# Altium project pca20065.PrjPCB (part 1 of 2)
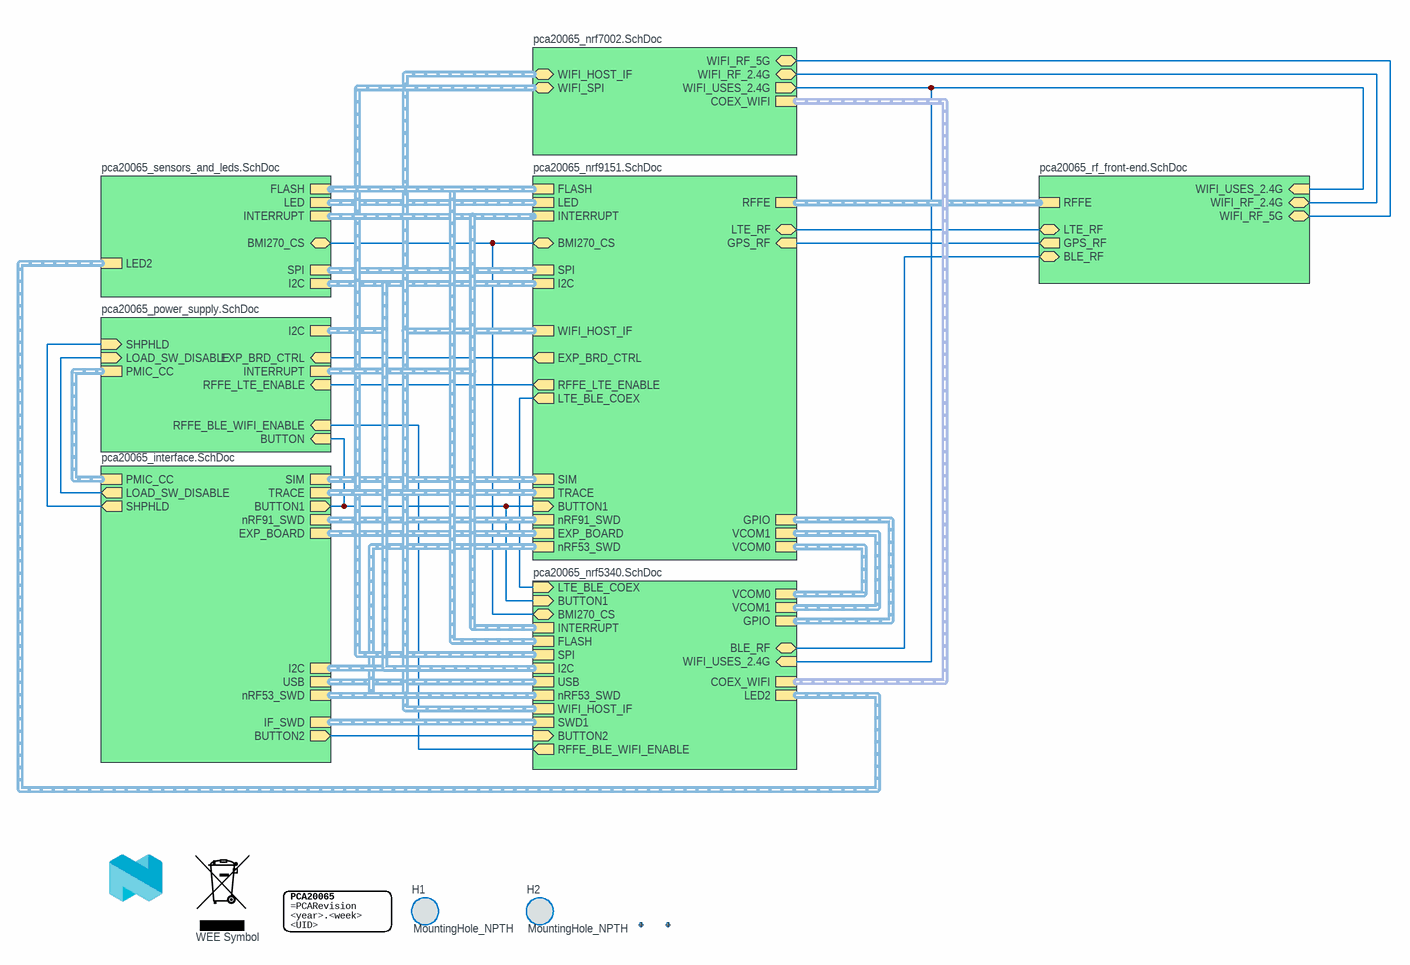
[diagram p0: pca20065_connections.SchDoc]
SurfaceFinish: ENIG Gold; SoldermaskColor: Blue; SilkscreenColor: White; ProjectNumber: 4492; ProjectName: Thingy91v2; ProductName: Thingy:91 X; PCBStackup: 6001; PCBRevision: 0229GETR; PCBNumber: 400796; PCARevision: 2.0.0; PCAName: PCA20065; Organization: Nordic Semiconductor; NrOfLayers: 6; Dielectric: FR-4; Designer: GETR; Compliance: RoHS, REACH, Halogen-Free; Classification: Public; BoardTitle: Thingy:91 X; BoardThickness: 1.6mm
10 sheets, 319 parts. Net scope: hierarchical (ports join the sheet entries above them; power ports are global).
Board file: 400796.PcbDoc
Sheets:
  pca20065_connections.SchDoc
     = pca20065_nrf9151.SchDoc
     = pca20065_sensors_and_leds.SchDoc
     = pca20065_nrf5340.SchDoc
     = pca20065_interface.SchDoc
      S1 = pca20065_switch_fsa.SchDoc
      S9 = pca20065_switch_nx.SchDoc
     = pca20065_power_supply.SchDoc
     = pca20065_rf_front-end.SchDoc
     = pca20065_nrf7002.SchDoc

## Sheet pca20065_connections.SchDoc: =BoardTitle + ' - Connections'
size A3; Organization: Nordic Semiconductor; DocumentNumber: 1; Revision: 2.0.0; SheetNumber: 1; SheetTotal: 10; Author: GETR; CompanyName: Nordic Semiconductor; DrawnBy: GETR; DocumentSize: A3

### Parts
Fid1  Fiducial mark  [Fiducial_Round-Square]  (value not drawn)
Fid2  Fiducial mark  [Fiducial_Round-Square]  (value not drawn)
H1  MountingHole_NPTH  [MountingHole_3.2_M3]  (no BOM)
H2  MountingHole_NPTH  [MountingHole_3.2_M3]  (no BOM)
LABEL1  12x38mm  [LabelSilk_12x38]  (value not drawn)
LOGO1  WEE Symbol  [WEE_3x4.5mm]  (no BOM)
LOGO2  Nordic Logo  [NORDIC_LOGO_LYING]  (value not drawn)  (no BOM)

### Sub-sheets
? = pca20065_nrf9151.SchDoc: SIM (harness SIM), nRF91_SWD (harness SWD), VCOM0 (harness UART), I2C (harness I2C), BUTTON1 (in), LED (harness LED), SPI (harness SPI), BMI270_CS (bidir), nRF53_SWD (harness SWD), EXP_BOARD (harness EXP_BOARD), GPS_RF (in), LTE_RF (bidir), RFFE (harness RFFE), VCOM1 (harness UART), FLASH (harness MEMORY), WIFI_HOST_IF (harness WIFI_HOST_IF), INTERRUPT (harness INT), EXP_BRD_CTRL (out), TRACE (harness TRACE), RFFE_LTE_ENABLE (out), LTE_BLE_COEX (out), GPIO (harness GPIO)
? = pca20065_sensors_and_leds.SchDoc: I2C (harness I2C), LED (harness LED), SPI (harness SPI), BMI270_CS (bidir), LED2 (harness LED), FLASH (harness MEMORY), INTERRUPT (harness INT)
? = pca20065_nrf5340.SchDoc: USB (harness USB), COEX_WIFI (harness COEX), WIFI_HOST_IF (harness WIFI_HOST_IF), I2C (harness I2C), VCOM0 (harness UART), nRF53_SWD (harness SWD), BUTTON2 (in), BLE_RF (bidir), LED2 (harness LED), VCOM1 (harness UART), BMI270_CS (bidir), INTERRUPT (harness INT), WIFI_USES_2.4G (in), SPI (harness SPI), LTE_BLE_COEX (in), SWD1 (harness SWD), BUTTON1 (in), GPIO (harness GPIO), RFFE_BLE_WIFI_ENABLE (out), FLASH (harness MEMORY)
? = pca20065_interface.SchDoc: SIM (harness SIM), nRF53_SWD (harness SWD), nRF91_SWD (harness SWD), BUTTON1 (out), USB (harness USB), BUTTON2 (out), LOAD_SW_DISABLE (out), EXP_BOARD (harness EXP_BOARD), SHPHLD (out), PMIC_CC (harness CC), I2C (harness I2C), TRACE (harness TRACE), IF_SWD (harness SWD)
? = pca20065_power_supply.SchDoc: I2C (harness I2C), LOAD_SW_DISABLE (in), SHPHLD (in), PMIC_CC (harness CC), BUTTON (in), EXP_BRD_CTRL (in), INTERRUPT (harness INT), RFFE_LTE_ENABLE (in), RFFE_BLE_WIFI_ENABLE (in)
? = pca20065_rf_front-end.SchDoc: RFFE (harness RFFE), GPS_RF (out), LTE_RF (bidir), BLE_RF (bidir), WIFI_RF_2.4G (bidir), WIFI_RF_5G (bidir), WIFI_USES_2.4G (in)
? = pca20065_nrf7002.SchDoc: WIFI_SPI (bidir, harness SPI), WIFI_USES_2.4G (out), WIFI_HOST_IF (bidir, harness WIFI_HOST_IF), WIFI_RF_2.4G (bidir), WIFI_RF_5G (bidir), COEX_WIFI (harness COEX)

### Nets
2.4G_SW_CTRL: sheet /WIFI_USES_2.4G, sheet /WIFI_USES_2.4G, sheet /WIFI_USES_2.4G
BMI270_CS: sheet /BMI270_CS, sheet /BMI270_CS, sheet /BMI270_CS
LTE_BLE_COEX: sheet /RFFE_LTE_ENABLE, sheet /LTE_BLE_COEX, sheet /LTE_BLE_COEX, sheet /RFFE_LTE_ENABLE
RFFE_BLE_WIFI_ENABLE: sheet /RFFE_BLE_WIFI_ENABLE, sheet /RFFE_BLE_WIFI_ENABLE
SHPHLD: sheet /SHPHLD, sheet /SHPHLD
NetCR1_2: sheet /BLE_RF, sheet /BLE_RF
NetF2_3: sheet /WIFI_RF_5G, sheet /WIFI_RF_5G
NetJ1_1: sheet /LTE_RF, sheet /LTE_RF
NetM1_44: sheet /BUTTON1, sheet /BUTTON1, sheet /BUTTON1, sheet /BUTTON
NetM1_59: sheet /EXP_BRD_CTRL, sheet /EXP_BRD_CTRL
NetP9_10: sheet /LOAD_SW_DISABLE, sheet /LOAD_SW_DISABLE
NetQ6_6: sheet /BUTTON2, sheet /BUTTON2
NetU9_5: sheet /GPS_RF, sheet /GPS_RF
NetU21_9: sheet /WIFI_RF_2.4G, sheet /WIFI_RF_2.4G

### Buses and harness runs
harness sheet /IF_SWD = sheet /SWD1
harness sheet /SPI = sheet /WIFI_SPI

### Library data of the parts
Fid1 Fid2 = Fid-Mark-Round-Square: Manufacturer: N.A.; Part number NEMS: 100500075; Value: N.A.; Pad Count: 1; Component Status: Active; System: Connector
H1 H2 = MountingHole_3.2_M3: Mounting hole, 3.2mm, M3, no annular; Manufacturer: N.A.; Part number NEMS: 101200008; Pad Count: 0; Component Status: Active; Rule: UNIONINDEX=0¦RULEKIND=Clearance¦NETSCOPE=DifferentNets¦LAYERKIND=SameLayer¦NAME=Schematic Clearance Constraint¦GAP=10mil¦GENERICCLEARANCE=10mil¦IGNOREPADTOPADCLEARANCEINFOOTPRINT=TRUE¦OBJECTCLEARANCES=ClearanceObj_Arc-ClearanceObj_Hole:0;ClearanceObj_Track-ClearanceObj_Hole:0;ClearanceObj_SMDPad-ClearanceObj_Hole:0;ClearanceObj_THPad-ClearanceObj_Hole:0;ClearanceObj_Via-ClearanceObj_Hole:0;ClearanceObj_Fill-ClearanceObj_Hole:0;ClearanceObj_Poly-ClearanceObj_Hole:0;ClearanceObj_Region-ClearanceObj_Hole:0;ClearanceObj_Text-ClearanceObj_Hole:0¦UNIT=Metric; Rule: UNIONINDEX=0¦RULEKIND=RoutingVias¦NETSCOPE=AnyNet¦LAYERKIND=SameLayer¦NAME=Schematic Routing Via Style¦HOLEWIDTH=0mil¦WIDTH=0mil¦VIASTYLE=Through Hole¦MINHOLEWIDTH=0mil¦MINWIDTH=0mil¦MAXHOLEWIDTH=78.7402mil¦MAXWIDTH=78.7402mil¦UNIT=Metric
LABEL1 = Label_12x38: PCA version label, stick-on, 12x38mm; Manufacturer: Ellco Etikett; Manufacturer Part Number: 83019; Part number NEMS: 101200031; Component Status: Active; Pad Count: 0; Note: N.A.
LOGO1 = WEEE Symbol 3x4.5mm: WEEE Directive symbol; Manufacturer: N.A.; Part number NEMS: 101100006; Component Status: Active; Pad Count: 0
LOGO2 = Nordic Logo lying: Manufacturer: N.A.; Part number NEMS: 101100001; Component Status: Active; Pad Count: 0

## Sheet pca20065_nrf9151.SchDoc: =BoardTitle + ' - nRF9151'
size A3; Organization: Nordic Semiconductor; DocumentNumber: 2; Revision: 2.0.0; SheetNumber: 2; SheetTotal: 10; Author: GETR; CompanyName: Nordic Semiconductor; DrawnBy: GETR; DocumentSize: A3
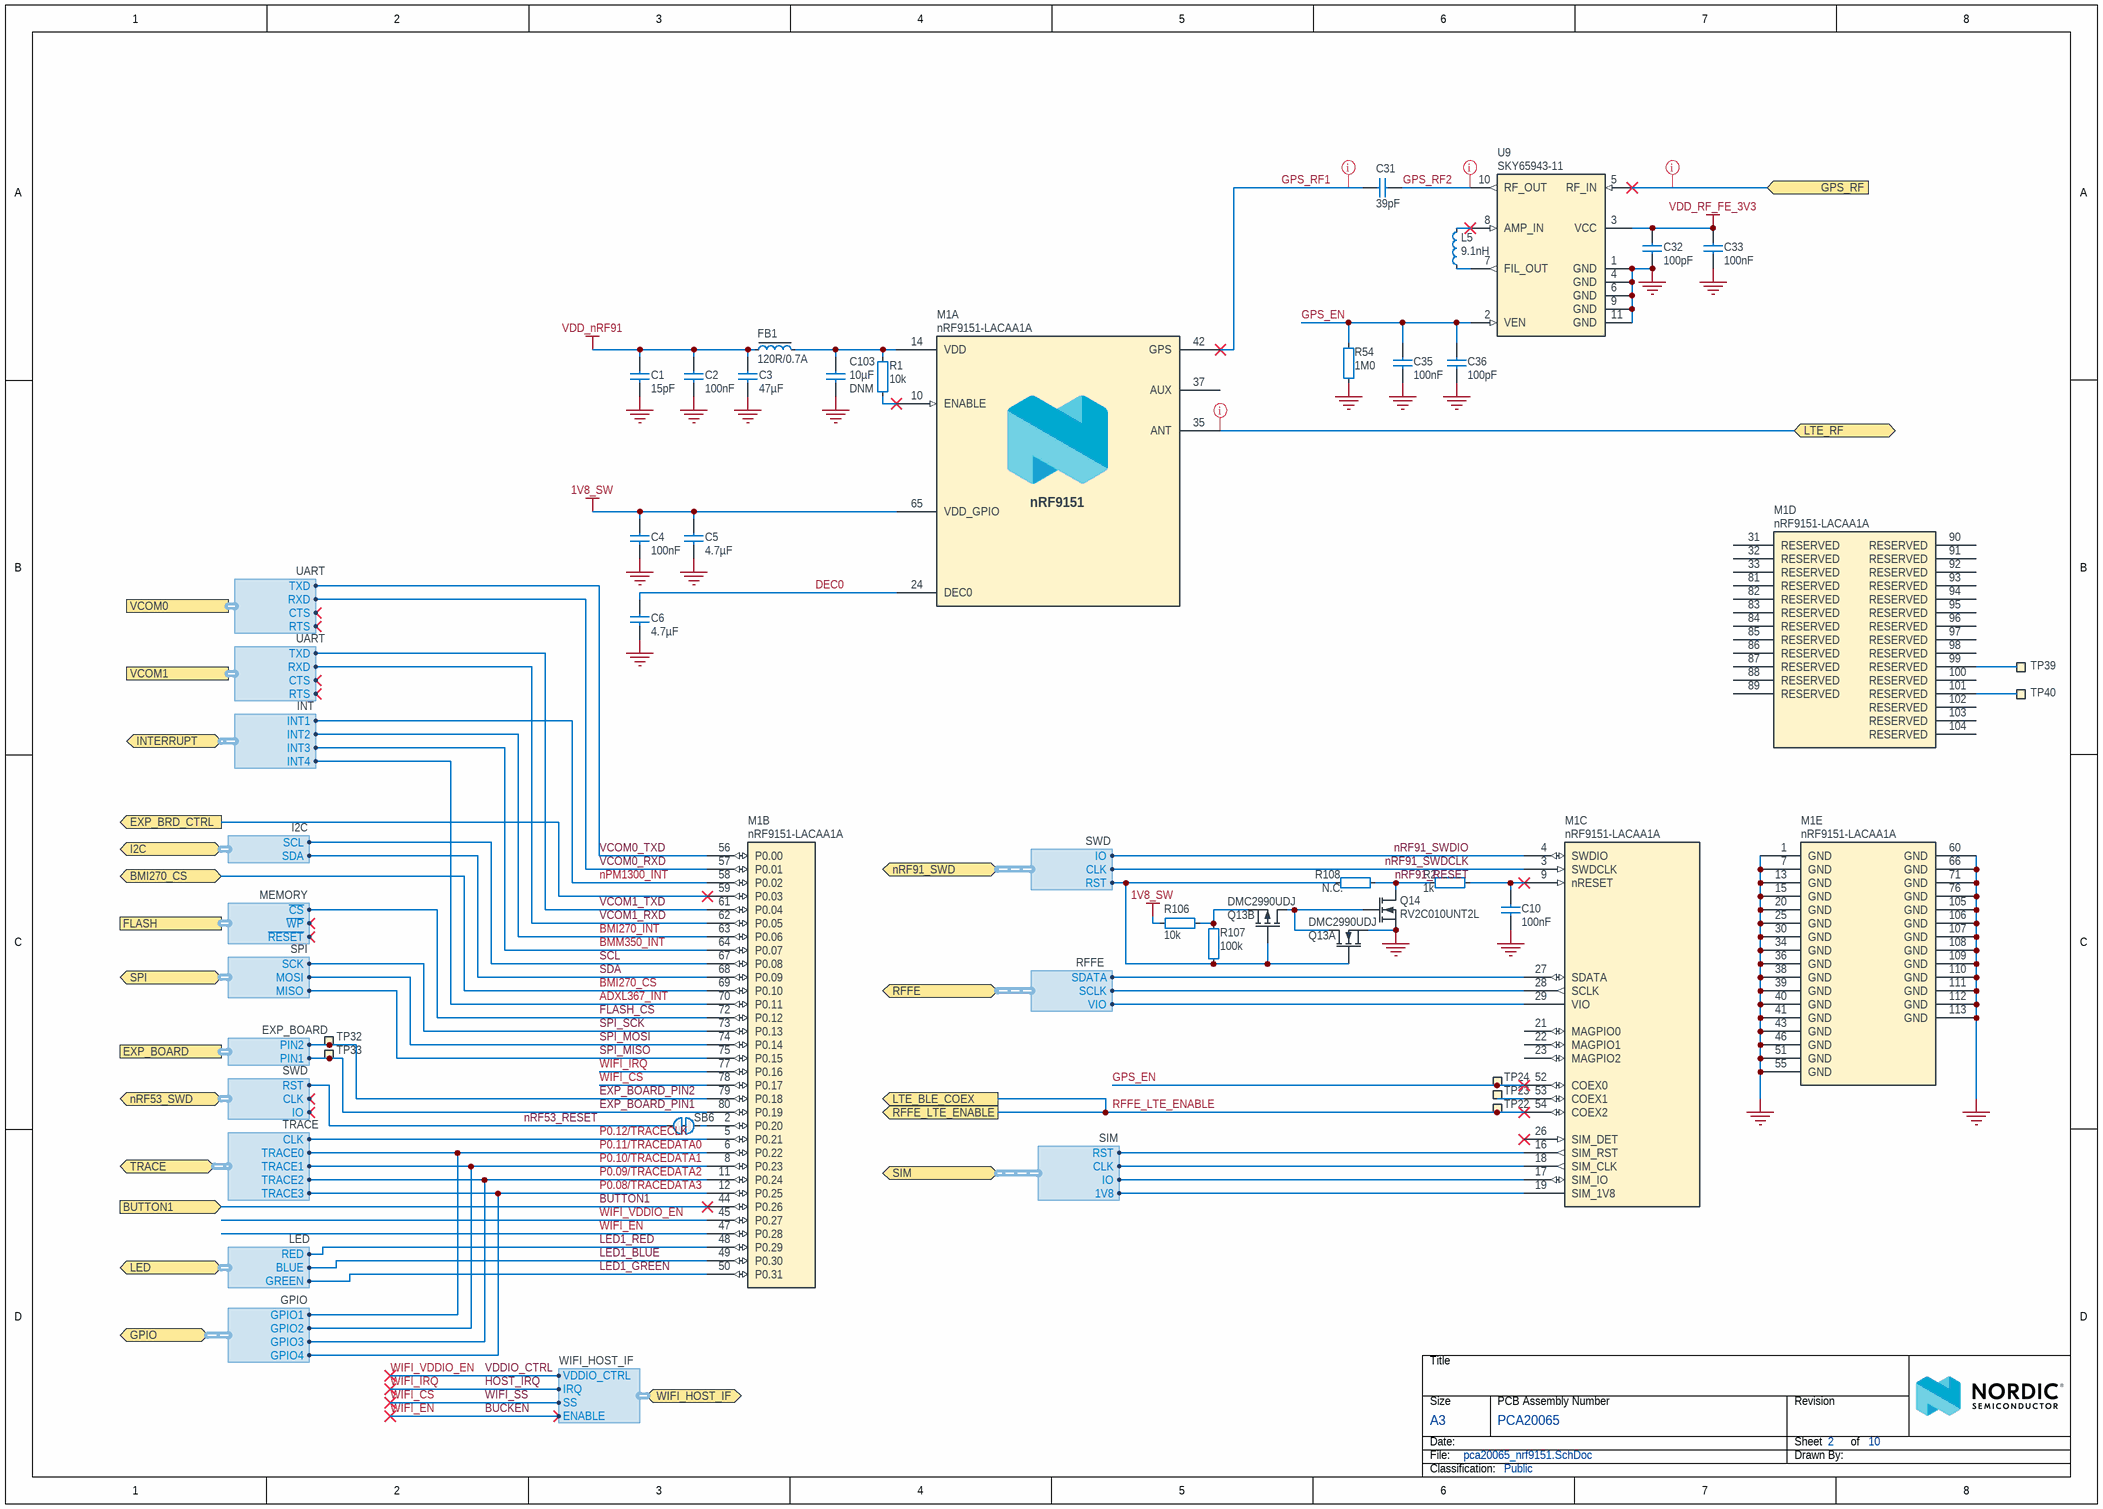
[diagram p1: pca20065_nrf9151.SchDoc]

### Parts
C1  15pF  [CAPC0603X03L_C]
C2  100nF  [CAPC0603X03L_C]
C3  47µF  [CAPC2012X11L]
C4  100nF  [CAPC0603X03L_C]
C5  4.7µF  [CAPC1005X04L]
C6  4.7µF  [CAPC2012X11L]
C10  100nF  [CAPC0603X03L_C]
C31  39pF  [CAPC0603X03L_C]
C32  100pF  [CAPC0603X03L_C]
C33  100nF  [CAPC0603X03L_C]
C35  100nF  [CAPC0603X03L_C]
C36  100pF  [CAPC0603X03L_C]
C103  10µF  Assembly: DNM  [CAPC1608X06L]
FB1  120R/0.7A  [INDC1608X06L]
L5  9.1nH  [INDC1005X04L_WW]
M1  nRF9151-LACAA1A  [LGA50P1210X1110X130-113N]  (parts A,B,C,D,E of 5)
Q13  DMC2990UDJ  [DMx299UDJ]  (parts A,B of 2)
Q14  RV2C010UNT2L  [DFN65P100X40-3L]
R1  10k  [RESC0603X03L_C]
R2  1k  [RESC0603X03L_C]
R54  1M0  [RESC0603X03L_C]
R106  10k  [RESC0603X03L_C]
R107  100k  [RESC0603X03L_C]
R108  N.C.  [RESC0603X03L_C_NC]
SB6  Solderbridge  [Solderbridge_Shorted]  (value not drawn)  (net tie, no BOM)
TP22  Ø1.0mm,SMD  [TP_SMD_D1.0mm]  (value not drawn)  (no BOM)
TP23  Ø1.0mm,SMD  [TP_SMD_D1.0mm]  (value not drawn)  (no BOM)
TP24  Ø1.0mm,SMD  [TP_SMD_D1.0mm]  (value not drawn)  (no BOM)
TP32  Ø1.5mm,SMD  [TP_SMD_D1.5mm]  (value not drawn)  (no BOM)
TP33  Ø1.5mm,SMD  [TP_SMD_D1.5mm]  (value not drawn)  (no BOM)
TP39  Ø0.7mm,SMD  [TP_SMD_D0.7mm]  (value not drawn)  (no BOM)
TP40  Ø0.7mm,SMD  [TP_SMD_D0.7mm]  (value not drawn)  (no BOM)
U9  SKY65943-11  [SKY65943-11]

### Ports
BMI270_CS (bidir), BUTTON1 (in), EXP_BOARD (harness EXP_BOARD), EXP_BRD_CTRL (out), FLASH (harness MEMORY), GPIO (bidir, harness GPIO), GPS_RF (in), I2C (bidir, harness I2C), INTERRUPT (bidir, harness INT), LED (bidir, harness LED), LTE_BLE_COEX (out), LTE_RF (bidir), nRF53_SWD (bidir, harness SWD), nRF91_SWD (bidir, harness SWD), RFFE (bidir, harness RFFE), RFFE_LTE_ENABLE (out), SIM (bidir, harness SIM), SPI (bidir, harness SPI), TRACE (bidir, harness TRACE), VCOM0 (harness UART), VCOM1 (harness UART), WIFI_HOST_IF (bidir, harness WIFI_HOST_IF)

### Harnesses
I2C: SDA, SCL
LED: BLUE, GREEN, RED
SWD: IO, CLK, RST
SIM: RST, CLK, IO, 1V8
EXP_BOARD: PIN1, PIN2
RFFE: VIO, SCLK, SDATA
UART: RTS, CTS, RXD, TXD
MEMORY: ~{CS}, ~{WP}, ~{RESET}
WIFI_HOST_IF: SS, IRQ, ENABLE, VDDIO_CTRL
INT: INT2, INT3, INT1, INT4
TRACE: TRACE3, TRACE2, TRACE1, TRACE0, CLK
SPI: MISO, MOSI, SCK
GPIO: GPIO2, GPIO3, GPIO1, GPIO4

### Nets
1V8_SW: C4.1 C5.1 M1.65(VDD_GPIO) R106.1
GND: C1.2 C2.2 C3.2 C4.2 C5.2 C6.2 C10.2 C32.1 C33.1 C35.1 C36.1 C103.1 M1.1(GND) M1.7(GND) M1.13(GND) M1.15(GND) M1.20(GND) M1.25(GND) M1.30(GND) M1.34(GND) M1.36(GND) M1.38(GND) M1.39(GND) M1.40(GND) M1.41(GND) M1.43(GND) M1.46(GND) M1.51(GND) M1.55(GND) M1.60(GND) M1.66(GND) M1.71(GND) M1.76(GND) M1.105(GND) M1.106(GND) M1.107(GND) M1.108(GND) M1.109(GND) M1.110(GND) M1.111(GND) M1.112(GND) M1.113(GND) Q13.1(S1) Q14.2(S) R54.1 U9.1(GND) U9.4(GND) U9.6(GND) U9.9(GND) U9.11(GND)
VDD_nRF91: C1.1 C2.1 C3.1 FB1.1
VDD_RF_FE_3V3: C32.2 C33.2 U9.3(VCC)
ADXL367_INT: M1.70(P0.11) ; port INTERRUPT.INT4
BMI270_CS: M1.69(P0.10) ; port BMI270_CS
BMI270_INT: M1.63(P0.06) ; port INTERRUPT.INT2
BMM350_INT: M1.64(P0.07) ; port INTERRUPT.INT3
DEC0: C6.1 M1.24(DEC0)
EXP_BOARD.PIN1: M1.80(P0.19) TP33.1 ; port EXP_BOARD.PIN1
EXP_BOARD.PIN2: M1.79(P0.18) TP32.1 ; port EXP_BOARD.PIN2
FLASH_~{CS}: M1.72(P0.12) ; port FLASH.~{CS}
GPS_EN: C35.2 C36.2 M1.52(COEX0) R54.2 TP24.1 U9.2(VEN)
GPS_RF1: C31.2 M1.42(GPS)
GPS_RF2: C31.1 U9.10(RF_OUT)
MISO: M1.75(P0.15) ; port SPI.MISO
MOSI: M1.74(P0.14) ; port SPI.MOSI
nPM1300_INT: M1.58(P0.02) ; port INTERRUPT.INT1
P0.08/TRACEDATA3: M1.12(P0.25) ; port TRACE.TRACE3, port GPIO.GPIO4
P0.09/TRACEDATA2: M1.11(P0.24) ; port TRACE.TRACE2, port GPIO.GPIO3
P0.10/TRACEDATA1: M1.8(P0.23) ; port TRACE.TRACE1, port GPIO.GPIO2
P0.11/TRACEDATA0: M1.6(P0.22) ; port TRACE.TRACE0, port GPIO.GPIO1
P0.12/TRACECLK: M1.5(P0.21) ; port TRACE.CLK
QSPI_CLK: M1.73(P0.13) ; port SPI.SCK
RFFE_LTE_ENABLE: M1.54(COEX2) TP22.1 ; port RFFE_LTE_ENABLE, port LTE_BLE_COEX  [project net LTE_BLE_COEX]
SCL: M1.67(P0.08) ; port I2C.SCL
SDA: M1.68(P0.09) ; port I2C.SDA
SIM.1V8: M1.19(SIM_1V8) ; port SIM.1V8
SIM.CLK: M1.18(SIM_CLK) ; port SIM.CLK
SIM.IO: M1.17(SIM_IO) ; port SIM.IO
SIM.RST: M1.16(SIM_RST) ; port SIM.RST
VCOM0.RXD: M1.57(P0.01) ; port VCOM0.RXD
VCOM0.TXD: M1.56(P0.00) ; port VCOM0.TXD
VCOM1.RXD: M1.62(P0.05) ; port VCOM1.RXD
VCOM1.TXD: M1.61(P0.04) ; port VCOM1.TXD
WIFI_CS: M1.78(P0.17) ; port WIFI_HOST_IF.SS  [project net QSPI_SS]
WIFI_EN: M1.47(P0.28) ; port WIFI_HOST_IF.ENABLE  [project net BUCKEN]
WIFI_IRQ: M1.77(P0.16) ; port WIFI_HOST_IF.IRQ  [project net HOST_IRQ]
WIFI_VDDIO_EN: M1.45(P0.27) ; port WIFI_HOST_IF.VDDIO_CTRL  [project net VDDIO_CTRL]
NetC10_1: C10.1 M1.9(nRESET) R2.2
NetC103_2: C103.2 FB1.2 M1.14(VDD) R1.1
NetJ1_1: M1.35(ANT) ; port LTE_RF
NetL5_1: L5.1 U9.8(AMP_IN)
NetL5_2: L5.2 U9.7(FIL_OUT)
NetM1_2: M1.2(P0.20) SB6.1
NetM1_3: M1.3(SWDCLK) ; port nRF91_SWD.CLK
NetM1_4: M1.4(SWDIO) ; port nRF91_SWD.IO
NetM1_10: M1.10(ENABLE) R1.2
NetM1_27: M1.27(SDATA) ; port RFFE.SDATA
NetM1_28: M1.28(SCLK) ; port RFFE.SCLK
NetM1_29: M1.29(VIO) ; port RFFE.VIO
NetM1_44: M1.44(P0.26) ; port BUTTON1
NetM1_48: M1.48(P0.29) ; port LED.RED
NetM1_49: M1.49(P0.30) ; port LED.BLUE
NetM1_50: M1.50(P0.31) ; port LED.GREEN
NetM1_53: M1.53(COEX1) TP23.1
NetM1_59: M1.59(P0.03) ; port EXP_BRD_CTRL
NetM1_99: M1.99(RESERVED) TP39.1
NetM1_101: M1.101(RESERVED) TP40.1
NetQ13_2: Q13.2(G1) Q13.5(G2) R107.1 R108.1 ; port nRF91_SWD.RST
NetQ13_3: Q13.3(D2) Q13.6(D1) Q14.1(G)
NetQ13_4: Q13.4(S2) R106.2 R107.2
NetQ14_3: Q14.3(D) R2.1 R108.2
NetSB6_2: SB6.2 ; port nRF53_SWD.RST
NetU9_5: U9.5(RF_IN) ; port GPS_RF

Not connected (* = marked no-connect by the designer): M1 21(MAGPIO0) 22(MAGPIO1) 23(MAGPIO2) 26(SIM_DET)* 31(RESERVED) 32(RESERVED) 33(RESERVED) 37(AUX) 81(RESERVED) 82(RESERVED) 83(RESERVED) 84(RESERVED) 85(RESERVED) 86(RESERVED) 87(RESERVED) 88(RESERVED) 89(RESERVED) 90(RESERVED) 91(RESERVED) 92(RESERVED) 93(RESERVED) 94(RESERVED) 95(RESERVED) 96(RESERVED) 97(RESERVED) 98(RESERVED) 100(RESERVED) 102(RESERVED) 103(RESERVED) 104(RESERVED)

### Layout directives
net class RF: GPS_RF1, GPS_RF2, NetJ1_1, NetU9_5

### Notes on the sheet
- VCOM0_TXD
- nRF91_SWDIO
- VCOM0_RXD
- VCOM1_RXD
- VCOM1_TXD
- nRF91_SWDCLK
- (near R2) nRF91_RESET
- SCL
- SDA
- SPI_SCK
- SPI_MOSI
- SPI_MISO
- FLASH_CS
- (near SB6) EXP_BOARD_PIN1
- (near SB6) EXP_BOARD_PIN2
- (near SB6) nRF53_RESET
- BUTTON1
- LED1_RED
- LED1_BLUE
- LED1_GREEN
- VDDIO_CTRL
- HOST_IRQ
- WIFI_SS
- BUCKEN

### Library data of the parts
C1 = C0201-15p: Capacitor, NP0, ±5%, 25V; Manufacturer: Murata; Manufacturer Part Number: GRM0335C1E150JA01D; Part number IPS: 00000003193; Part number NEMS: 100200034; Pad Count: 2; Component Status: Active; Artikkelnr Noca: N.A.
C2 C4 C10 = C0201-100n: Capacitor, X5R, ±10%; Manufacturer: N.A.; Part number IPS: 00000001248, 00000002505; Part number Norautron: 262071862; Part number NEMS: 100200078; Pad Count: 2; Component Status: Active; Note: 16V
C3 = C0805-47µ-10V: Capacitor, X5R, ±20%, 10V; Manufacturer: Murata; Manufacturer Part Number: GRM21BR61A476ME15; Part number IPS: 00000004759; Part number NEMS: 100200288; Pad Count: 2; Component Status: Active; Artikkelnr Noca: N.A.
C5 = C0402-4µ7: Capacitor, X5R, ±20%; Manufacturer: N.A.; Part number IPS: 00000001251, 00000007165; Part number NEMS: 100200193; Pad Count: 2; Component Status: Active; Note: 10V; Artikkelnr Noca: 20039482
C6 = C0805-4µ7: Capacitor, X5R, ±10%, 16V; Manufacturer: N.A.; Part number IPS: 00000006289; Part number NEMS: 100200284; Pad Count: 2; Component Status: Active; Artikkelnr Noca: 20039266
C31 = C0201-39p: Capacitor, NP0, ±1%, 25V; Manufacturer: Murata; Manufacturer Part Number: GRM0335C1E390FA01D; Part number IPS: 00000001668; Part number NEMS: 100200039; Artikkelnr Noca: N.A.; Pad Count: 2; Component Status: Active
C32 C36 = C0201-100p: Capacitor, NP0, ±2%, 25V; Manufacturer: Murata; Manufacturer Part Number: GRM0335C1E101GA01D; Part number IPS: 00000007853; Part number NEMS: 100200044; Artikkelnr Noca: N.A.; Pad Count: 2; Component Status: Active
C33 C35 = C0201-100n: Capacitor, X5R, ±10%; Manufacturer: N.A.; Part number IPS: 00000001248, 00000002505; Part number Norautron: 262071862; Part number NEMS: 100200078; Note: 16V; Pad Count: 2; Component Status: Active
C103 = C0603-10µ-10V-X6S: Capacitor, X6S, ±10%; Manufacturer: N.A.; Part number NEMS: 100200470; Component Status: Active; Pad Count: 2; Note: 10V
FB1 = FB0402-120R@100M-700mA: Ferrite Bead, 120 Ohm @ 100MHz, 700mA, 130 mOhm Max; Manufacturer: Murata; Manufacturer Part Number: BLM15AX121SN1; Part number IPS: 00000004487; Part number NEMS: 100300100; Component Status: Active; Pad Count: 2; Note: N.A.
L5 = L0402-9n1-Wirewound-Murata: Inductor, 540mA, ±2%, 140mΩ, Q=25; Manufacturer: Murata; Manufacturer Part Number: LQW15AN9N1G00; Part number IPS: 00000002497; Part number NEMS: 100300357; Note: -55°C ~ 125°C; Artikkelnr Noca: N.A.; Pad Count: 2; Component Status: Active
M1 = nRF9151-LACAA1A: Low power System-in-Package with integrated LTE-M/NB-IoT modem and GPS; Manufacturer: Nordic Semiconductor; Part number NEMS: 102000407; Component Status: Active; Pad Count: 113; Note: N.A.
Q13 = DMC2990UDJ-7: MOSFET, Dual N and P-Channel, 20V, 450mA/310mA, 990mOhm, 350mW; Manufacturer: Diodes Incorporated; Part number IPS: 00000004489; Part number Norautron: 26470028; Part number NEMS: 101300174; Note: N.A.; Pad Count: 6; Component Status: Active
Q14 = RV2C010UNT2L: N-Channel MOSFET, 20V, 1A, 470mOhm, 400mW; Manufacturer: Rohm Semiconductor; Part number IPS: 00000009976; Part number Norautron: 26320026; Part number NEMS: 101300132; Note: N.A.; Artikkelnr Noca: 35010020; Pad Count: 3; Component Status: Active
R1 = R0201-10k: Resistor, ±1%, 0.05W; Manufacturer: N.A.; Part number IPS: 00000001255; Part number Norautron: 26107101; Part number NEMS: 100100065; Pad Count: 2; Component Status: Active; Note: Chip Res 1%
R2 = R0201-1k0: Resistor, ±1%, 0.05W; Manufacturer: N.A.; Part number IPS: 00000005786; Part number NEMS: 100100043; Note: Chip Res 1%; Pad Count: 2; Component Status: Active
R54 = R0201-1M0: Resistor, ±1%, 0.05W; Manufacturer: N.A.; Part number IPS: 00000001418; Part number Norautron: 26107108; Part number NEMS: 100100093; Note: Chip Res 1%; Pad Count: 2; Component Status: Active
R106 = R0201-10k: Resistor, ±1%, 0.05W; Manufacturer: N.A.; Part number IPS: 00000001255; Part number Norautron: 26107101; Part number NEMS: 100100065; Note: Chip Res 1%; Pad Count: 2; Component Status: Active
R107 = R0201-100k: Resistor, ±1%, 0.05W; Manufacturer: N.A.; Part number IPS: 00000001419; Part number Norautron: 26108487; Part number NEMS: 100100080; Note: Chip Res 1%; Pad Count: 2; Component Status: Active
R108 = R0201-N.C.: Not mounted; Manufacturer: N.A.; Part number NEMS: 100100107; Note: Chip Res; Assembly: Not mounted; Pad Count: 2; Component Status: Active
SB6 = Solderbridge Shorted: Shorted Solderbridge; Manufacturer: N.A.; Part number NEMS: 100500459; Component Status: Active; Pad Count: 2; System: Connector
TP22-TP24 = TP_SMD_Ø1.0MM: 1.0mm circular SMD testpad; Manufacturer: Nordic Semiconductor; Manufacturer Part Number: N.A.; Part number NEMS: 100500475; Pad Count: 1; Component Status: Active
TP32 TP33 = TP_SMD_Ø1.5MM: 1.5mm circular SMD testpad; Manufacturer: Nordic Semiconductor; Manufacturer Part Number: N.A.; Part number NEMS: 100500477; Pad Count: 1; Component Status: Active
TP39 TP40 = TP_SMD_Ø0.7MM: 0.7mm circular SMD testpad; Manufacturer: Nordic Semiconductor; Manufacturer Part Number: N.A.; Part number NEMS: 100500474; Pad Count: 1; Component Status: Active
U9 = SKY65943-11: GNSS Low-Noise Amplifier Front-End Module with Integrated Pre-Filter and Post-Filter; Manufacturer: Skyworks; Part number IPS: 00000002997; Part number NEMS: 101900584; Note: N.A.; Pad Count: 10; Component Status: Active

## Sheet pca20065_sensors_and_leds.SchDoc: =BoardTitle + ' - Sensors and LEDs'
size A3; Organization: Nordic Semiconductor; DocumentNumber: 6; Revision: 2.0.0; SheetNumber: 6; SheetTotal: 10; Author: GETR; CompanyName: Nordic Semiconductor; DrawnBy: GETR; DocumentSize: A3
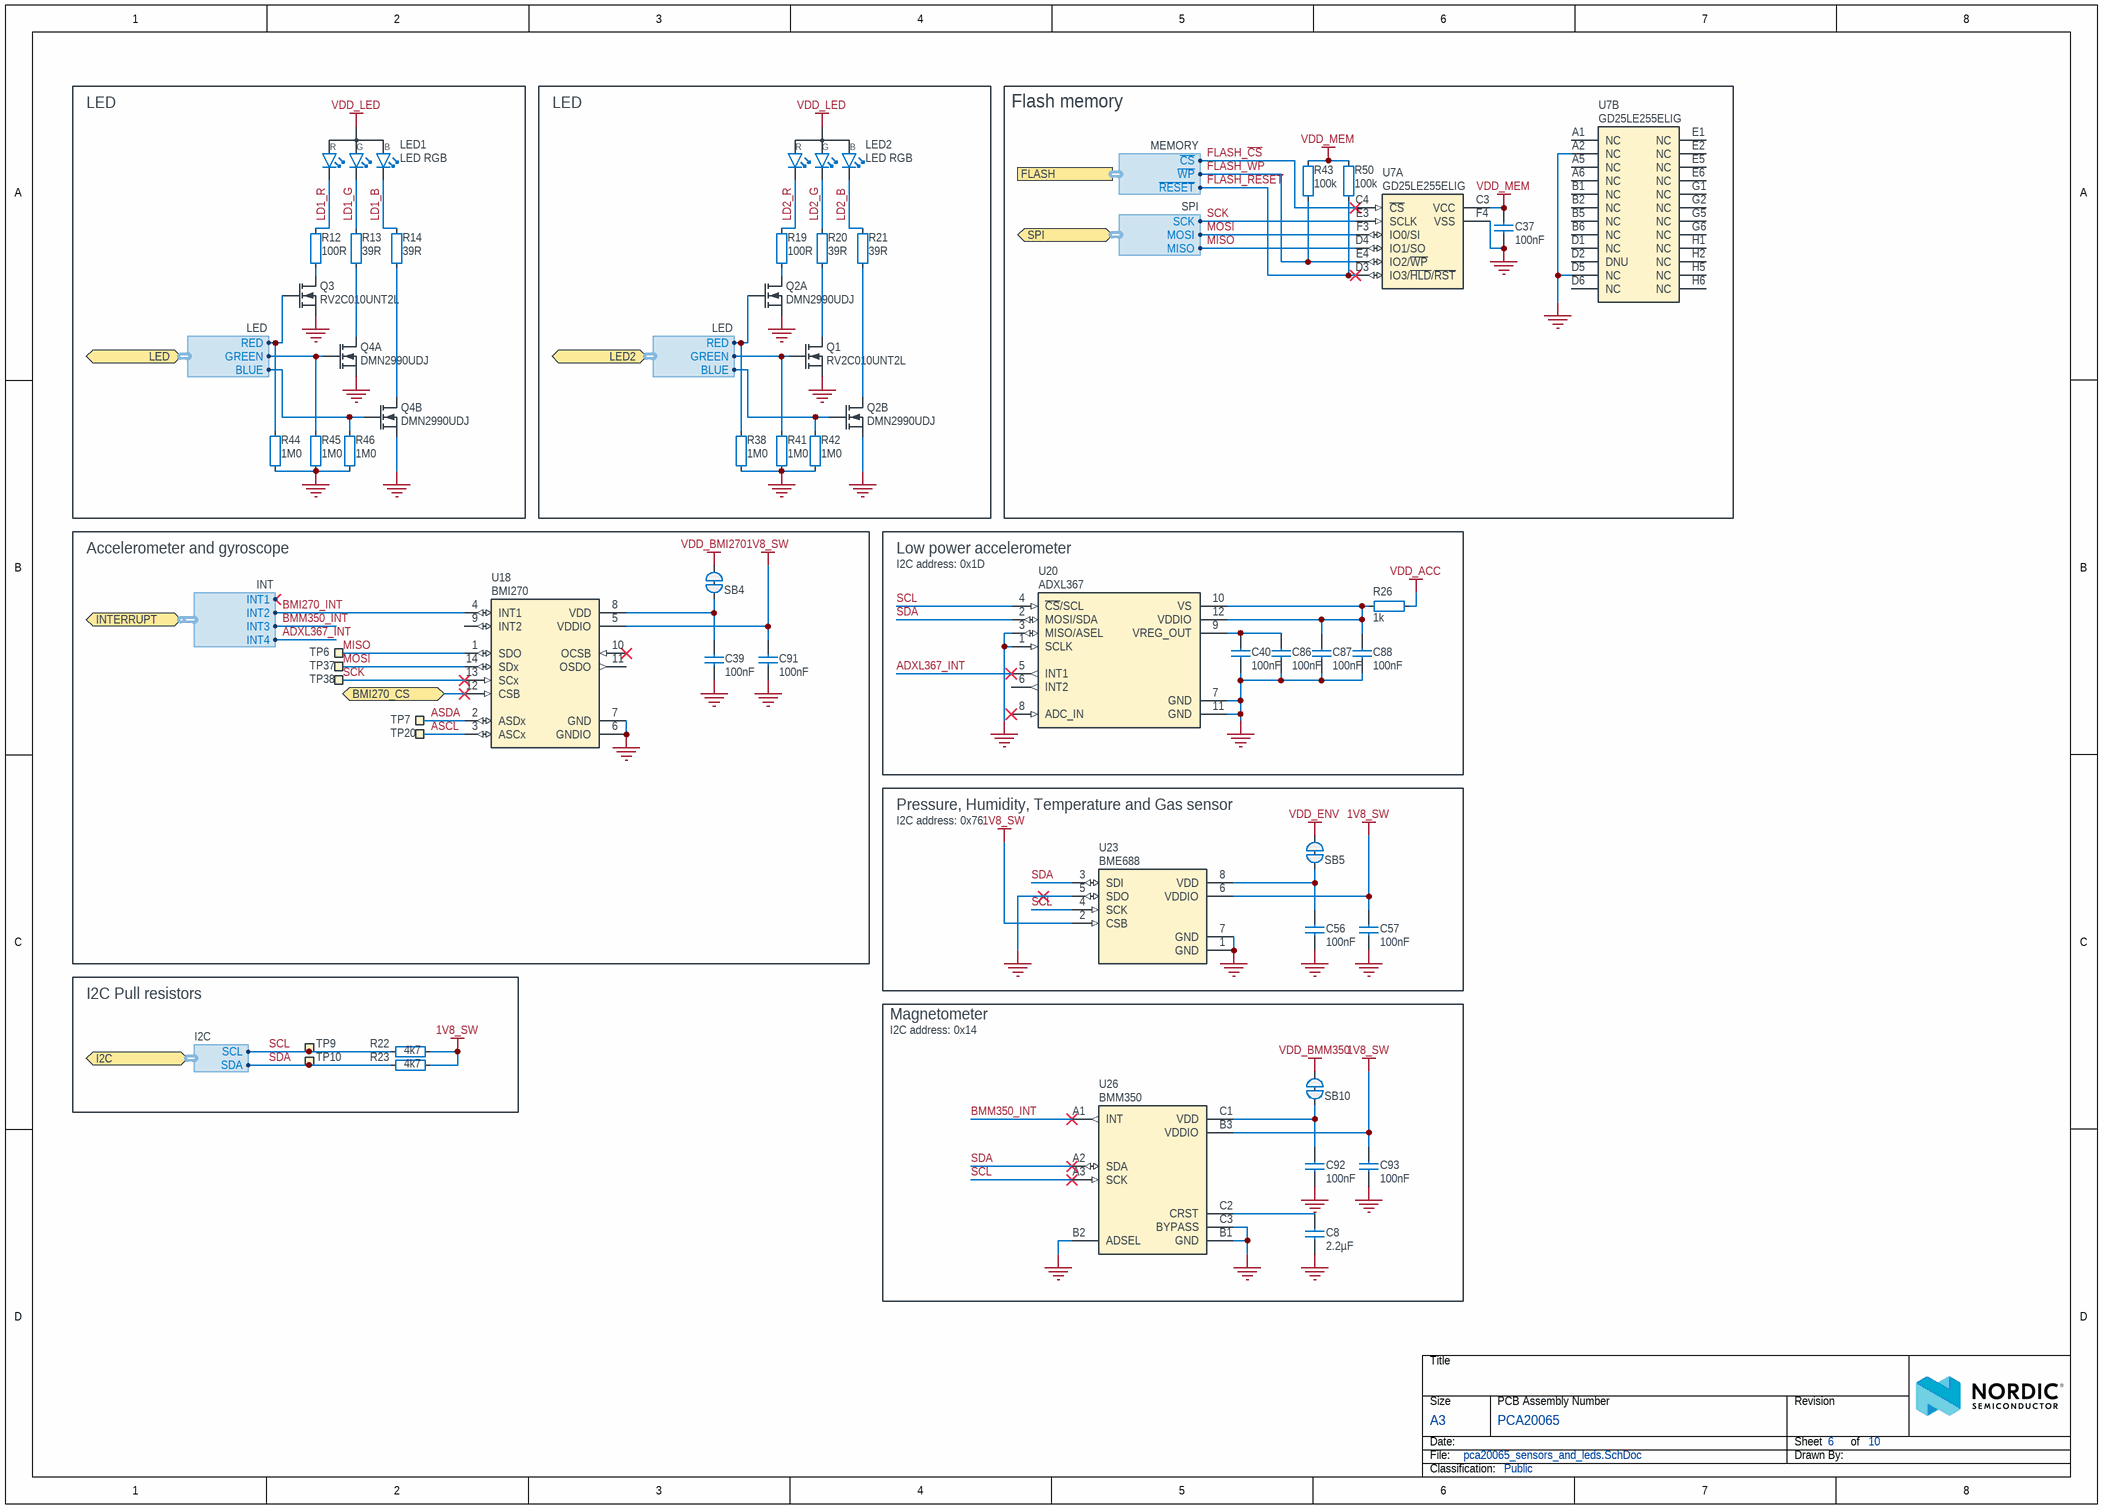
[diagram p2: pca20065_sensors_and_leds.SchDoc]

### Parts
C8  2.2µF  [CAPC1005X04L_C2]
C37  100nF  [CAPC0603X03L_C]
C39  100nF  [CAPC0603X03L_C]
C40  100nF  [CAPC0603X03L_C]
C56  100nF  [CAPC0603X03L_C]
C57  100nF  [CAPC0603X03L_C]
C86  100nF  [CAPC0603X03L_C]
C87  100nF  [CAPC0603X03L_C]
C88  100nF  [CAPC0603X03L_C]
C91  100nF  [CAPC0603X03L_C]
C92  100nF  [CAPC0603X03L_C]
C93  100nF  [CAPC0603X03L_C]
LED1  LED RGB  [LED_RGB_0606]
LED2  LED RGB  [OVSRRGBCC3_Side]
Q1  RV2C010UNT2L  [DFN65P100X40-3L]
Q2  DMN2990UDJ  [DMx299UDJ]  (parts A,B of 2)
Q3  RV2C010UNT2L  [DFN65P100X40-3L]
Q4  DMN2990UDJ  [DMx299UDJ]  (parts A,B of 2)
R12  100R  [RESC0603X03L_C]
R13  39R  [RESC0603X03L_C]
R14  39R  [RESC0603X03L_C]
R19  100R  [RESC0603X03L_C]
R20  39R  [RESC0603X03L_C]
R21  39R  [RESC0603X03L_C]
R22  4k7  [RESC0603X03L_C]
R23  4k7  [RESC0603X03L_C]
R26  1k  [RESC0603X03L_C]
R38  1M0  [RESC0603X03L_C]
R41  1M0  [RESC0603X03L_C]
R42  1M0  [RESC0603X03L_C]
R43  100k  [RESC0603X03L_C]
R44  1M0  [RESC0603X03L_C]
R45  1M0  [RESC0603X03L_C]
R46  1M0  [RESC0603X03L_C]
R50  100k  [RESC0603X03L_C]
SB4  Solderbridge  [Solderbridge_Shorted]  (value not drawn)  (net tie, no BOM)
SB5  Solderbridge  [Solderbridge_Shorted]  (value not drawn)  (net tie, no BOM)
SB10  Solderbridge  [Solderbridge_Shorted]  (value not drawn)  (net tie, no BOM)
TP6  Ø0.7mm,SMD  [TP_SMD_D0.7mm]  (value not drawn)  (no BOM)
TP7  Ø0.7mm,SMD  [TP_SMD_D0.7mm]  (value not drawn)  (no BOM)
TP9  Ø1.5mm,SMD  [TP_SMD_D1.5mm]  (value not drawn)  (no BOM)
TP10  Ø1.5mm,SMD  [TP_SMD_D1.5mm]  (value not drawn)  (no BOM)
TP20  Ø0.7mm,SMD  [TP_SMD_D0.7mm]  (value not drawn)  (no BOM)
TP37  Ø0.7mm,SMD  [TP_SMD_D0.7mm]  (value not drawn)  (no BOM)
TP38  Ø0.7mm,SMD  [TP_SMD_D0.7mm]  (value not drawn)  (no BOM)
U7  GD25LE255ELIG  [BGA32C50P6X8_350X400X50]  (parts A,B of 2)
U18  BMI270  [BMI270]
U20  ADXL367  [LGA50P220X230X97-12N]
U23  BME688  [BME680]
U26  BMM350  [BGA9C40P3X3_128X128X54]

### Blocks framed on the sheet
LED: LED1 Q3 Q4 R12-R14 R44-R46
LED: LED2 Q1 Q2 R19-R21 R38 R41 R42
Flash memory: C37 R43 R50 U7
Accelerometer and gyroscope: C39 C91 SB4 TP6 TP7 TP20 TP37 TP38 U18
Low power accelerometer: C40 C86-C88 R26 U20
Pressure, Humidity, Temperature and Gas sensor: C56 C57 SB5 U23
I2C Pull resistors: R22 R23 TP9 TP10
Magnetometer: C8 C92 C93 SB10 U26

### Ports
BMI270_CS (bidir), FLASH (harness MEMORY), I2C (bidir, harness I2C), INTERRUPT (bidir, harness INT), LED2 (bidir, harness LED), LED (bidir, harness LED), SPI (bidir, harness SPI)

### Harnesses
LED: BLUE, GREEN, RED
MEMORY: ~{CS}, ~{WP}, ~{RESET}
I2C: SDA, SCL
INT: INT2, INT3, INT1, INT4
SPI: MISO, MOSI, SCK

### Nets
1V8_SW: C57.2 C91.2 C93.2 R22.1 R23.1 U18.5(VDDIO) U23.2(CSB) U23.6(VDDIO) U26.B3(VDDIO)
GND: C8.1 C37.1 C39.1 C40.1 C56.1 C57.1 C86.1 C87.1 C88.1 C91.1 C92.1 C93.1 Q1.2(S) Q2.1(S1) Q2.4(S2) Q3.2(S) Q4.1(S1) Q4.4(S2) R38.1 R41.1 R42.1 R44.1 R45.1 R46.1 U7.A2(NC) U7.D5(NC) U7.F4(VSS) U18.6(GNDIO) U18.7(GND) U20.1(SCLK) U20.3(MISO/ASEL) U20.7(GND) U20.11(GND) U23.1(GND) U23.5(SDO) U23.7(GND) U26.B1(GND) U26.B2(ADSEL) U26.C3(BYPASS)
VDD_ACC: R26.1
VDD_BMI270: SB4.1
VDD_BMM350: SB10.1
VDD_ENV: SB5.1
VDD_LED: LED1.4(A) LED2.4(A)
VDD_MEM: C37.2 R43.2 R50.2 U7.C3(VCC)
ADXL367_INT: U20.5(INT1) ; port INTERRUPT.INT4
ASCL: TP20.1 U18.3(ASCx)
ASDA: TP7.1 U18.2(ASDx)
BMI270_CS: U18.12(CSB) ; port BMI270_CS
BMI270_INT: U18.4(INT1) ; port INTERRUPT.INT2
BMM350_INT: U26.A1(INT) ; port INTERRUPT.INT3
FLASH_~{CS}: U7.C4(~{CS}) ; port FLASH.~{CS}
FLASH_~{RESET}: R50.1 U7.D3(IO3/~{HLD}/~{RST}) ; port FLASH.~{RESET}
FLASH_~{WP}: R43.1 U7.E4(IO2/~{WP}) ; port FLASH.~{WP}
LD1_B: LED1.3(C_BLUE) R14.2
LD1_G: LED1.2(C_GREEN) R13.2
LD1_R: LED1.1(C_RED) R12.2
LD2_B: LED2.3(C_BLUE) R21.2
LD2_G: LED2.2(C_GREEN) R20.2
LD2_R: LED2.1(C_RED) R19.2
MISO: TP6.1 U7.D4(IO1/SO) U18.1(SDO) ; port SPI.MISO
MOSI: TP37.1 U7.F3(IO0/SI) U18.14(SDx) ; port SPI.MOSI
SCK: TP38.1 U7.E3(SCLK) U18.13(SCx) ; port SPI.SCK  [project net QSPI_CLK]
SCL: R22.2 TP9.1 U20.4(~{CS}/SCL) U23.4(SCK) U26.A3(SCK) ; port I2C.SCL
SDA: R23.2 TP10.1 U20.2(MOSI/SDA) U23.3(SDI) U26.A2(SDA) ; port I2C.SDA
NetC8_2: C8.2 U26.C2(CRST)
NetC39_2: C39.2 SB4.2 U18.8(VDD)
NetC40_2: C40.2 C86.2 U20.9(VREG_OUT)
NetC56_2: C56.2 SB5.2 U23.8(VDD)
NetC87_2: C87.2 C88.2 R26.2 U20.10(VS) U20.12(VDDIO)
NetC92_2: C92.2 SB10.2 U26.C1(VDD)
NetM1_48: Q3.1(G) R44.2 ; port LED.RED
NetM1_49: Q4.5(G2) R46.2 ; port LED.BLUE
NetM1_50: Q4.2(G1) R45.2 ; port LED.GREEN
NetQ1_1: Q1.1(G) R41.2 ; port LED2.GREEN
NetQ1_3: Q1.3(D) R20.1
NetQ2_2: Q2.2(G1) R38.2 ; port LED2.RED
NetQ2_3: Q2.3(D2) R21.1
NetQ2_5: Q2.5(G2) R42.2 ; port LED2.BLUE
NetQ2_6: Q2.6(D1) R19.1
NetQ3_3: Q3.3(D) R12.1
NetQ4_3: Q4.3(D2) R14.1
NetQ4_6: Q4.6(D1) R13.1

Not connected (* = marked no-connect by the designer): U7 A1(NC) A5(NC) A6(NC) B1(NC) B2(NC) B5(NC) B6(NC) D1(NC) D2(DNU) D6(NC) E1(NC) E2(NC) E5(NC) E6(NC) G1(NC) G2(NC) G5(NC) G6(NC) H1(NC) H2(NC) H5(NC) H6(NC) x(NC); U18 9(INT2) 10(OCSB)* 11(OSDO); U20 6(INT2) 8(ADC_IN)*

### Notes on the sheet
- (near U20) I2C address: 0x1D
- I2C address: 0x76
- I2C address: 0x14

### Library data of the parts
C8 = C0402-2µ2-10V-X7R-GRM155Z71A225KE44D: Capacitor, Ceramic, X7R, ±10%, 10V; Manufacturer: Murata; Part number NEMS: 100200653; Component Status: Active; Pad Count: 2; Note: -55°C ~ 125°C; Artikkelnr Noca: N.A.
C37 = C0201-100n: as C33 on sheet pca20065_nrf9151
C39 C91-C93 = C0201-100n-6.3V-X5R: Capacitor, Ceramic, X5R, ±10%, 6.3V; Manufacturer: Murata; Manufacturer Part Number: GRM033R60J104KE19D; Part number NEMS: 100200451; Artikkelnr Noca: N.A.; Pad Count: 2; Component Status: Active
C40 C56 C57 C86-C88 = C0201-100n: Capacitor, X5R, ±10%; Manufacturer: N.A.; Part number IPS: 00000001248, 00000002505; Part number Norautron: 262071862; Part number NEMS: 100200078; Note: 16V; Component Status: Active; Pad Count: 2
LED1 = LTST-C19HE1WT: RGB LED 1.60 mm x 1.60 mm SMD; Manufacturer: LITEON; Part number IPS: 00000007798; Part number NEMS: 101400093; Note: N.A.; Pad Count: 4; Component Status: Active
LED2 = OVSRRGBCC3_Side: Optek, Side mounted RGB 1204 SMD LED; Part number NEMS: 101400026; Pad Count: 4; Artikkelnr Noca: N.A.; Component Status: Active
Q1 Q3 = RV2C010UNT2L: as Q14 on sheet pca20065_nrf9151
Q2 Q4 = DMN2990UDJ-7: MOSFET, Dual N-Channel, 20V, 450mA, 990mOhm, 350mW; Manufacturer: Diodes Incorporated; Part number NEMS: 101300177; Note: N.A.; Pad Count: 6; Component Status: Active
R12 R19 = R0201-100: Resistor, ±1%, 0.05W; Manufacturer: N.A.; Part number IPS: 00000001794; Part number Norautron: 26107004; Part number NEMS: 100100027; Note: Chip Res 1%; Pad Count: 2; Component Status: Active
R13 R14 R20 R21 = R0201-39R: Resistor, ±1%, 0.05W; Manufacturer: N.A.; Part number IPS: 00000001704; Part number NEMS: 100100021; Note: Chip Res 1%; Pad Count: 2; Component Status: Active
R22 R23 = R0201-4k7: Resistor, ±1%, 0.05W; Manufacturer: N.A.; Part number IPS: 00000001706; Part number NEMS: 100100061; Note: Chip Res 1%; Pad Count: 2; Component Status: Active
R26 = R0201-1k0: as R2 on sheet pca20065_nrf9151
R38 R41 R42 R44-R46 = R0201-1M0: as R54 on sheet pca20065_nrf9151
R43 R50 = R0201-100k: Resistor, ±1%, 0.05W; Manufacturer: N.A.; Part number IPS: 00000001419; Part number Norautron: 26108487; Part number NEMS: 100100080; Pad Count: 2; Note: Chip Res 1%; Component Status: Active
SB4 SB5 SB10 = Solderbridge Shorted: as SB6 on sheet pca20065_nrf9151
TP6 TP7 TP20 TP37 TP38 = TP_SMD_Ø0.7MM: as TP39 on sheet pca20065_nrf9151
TP9 TP10 = TP_SMD_Ø1.5MM: as TP32 on sheet pca20065_nrf9151
U7 = GD25LE255ELIG: Quad Serial Flash, 256Mbit, 133MHz, 1.65V - 2.0V; Manufacturer: GigaDevice; Part number NEMS: 101900759; Note: N.A.; Pad Count: 32; Component Status: Active
U18 = BMI270: 6-axis, smart, low-power, inertial measurement unit; Manufacturer: Bosch; Part number NEMS: 101900620; Note: N.A.; Pad Count: 14; Component Status: Active
U20 = ADXL367BCCZ: Micropower, 3-Axis, ±2 g/±4 g/±8 g Digital Output MEMS Accelerometer; Manufacturer: Analog Devices; Part number NEMS: 101900775; Note: N.A.; Component Status: Active; Pad Count: 12
U23 = BME688: Low power gas, pressure, temperature & humidity sensor; Manufacturer: Bosch; Part number NEMS: 101900619; Note: N.A.; Component Status: Active; Pad Count: 8
U26 = BMM350: Magnetoresistive Sensor X, Y, Z Axis 9-WLCSP (1.28x1.28); Manufacturer: Bosch Sensortec; Part number NEMS: 101900817; Component Status: Active; Pad Count: 9; Note: N.A.

## Sheet pca20065_nrf5340.SchDoc: =BoardTitle + ' - nRF5340'
size A3; Organization: Nordic Semiconductor; DocumentNumber: 3; Revision: 2.0.0; SheetNumber: 3; SheetTotal: 10; Author: GETR; CompanyName: Nordic Semiconductor; DrawnBy: GETR; DocumentSize: A3
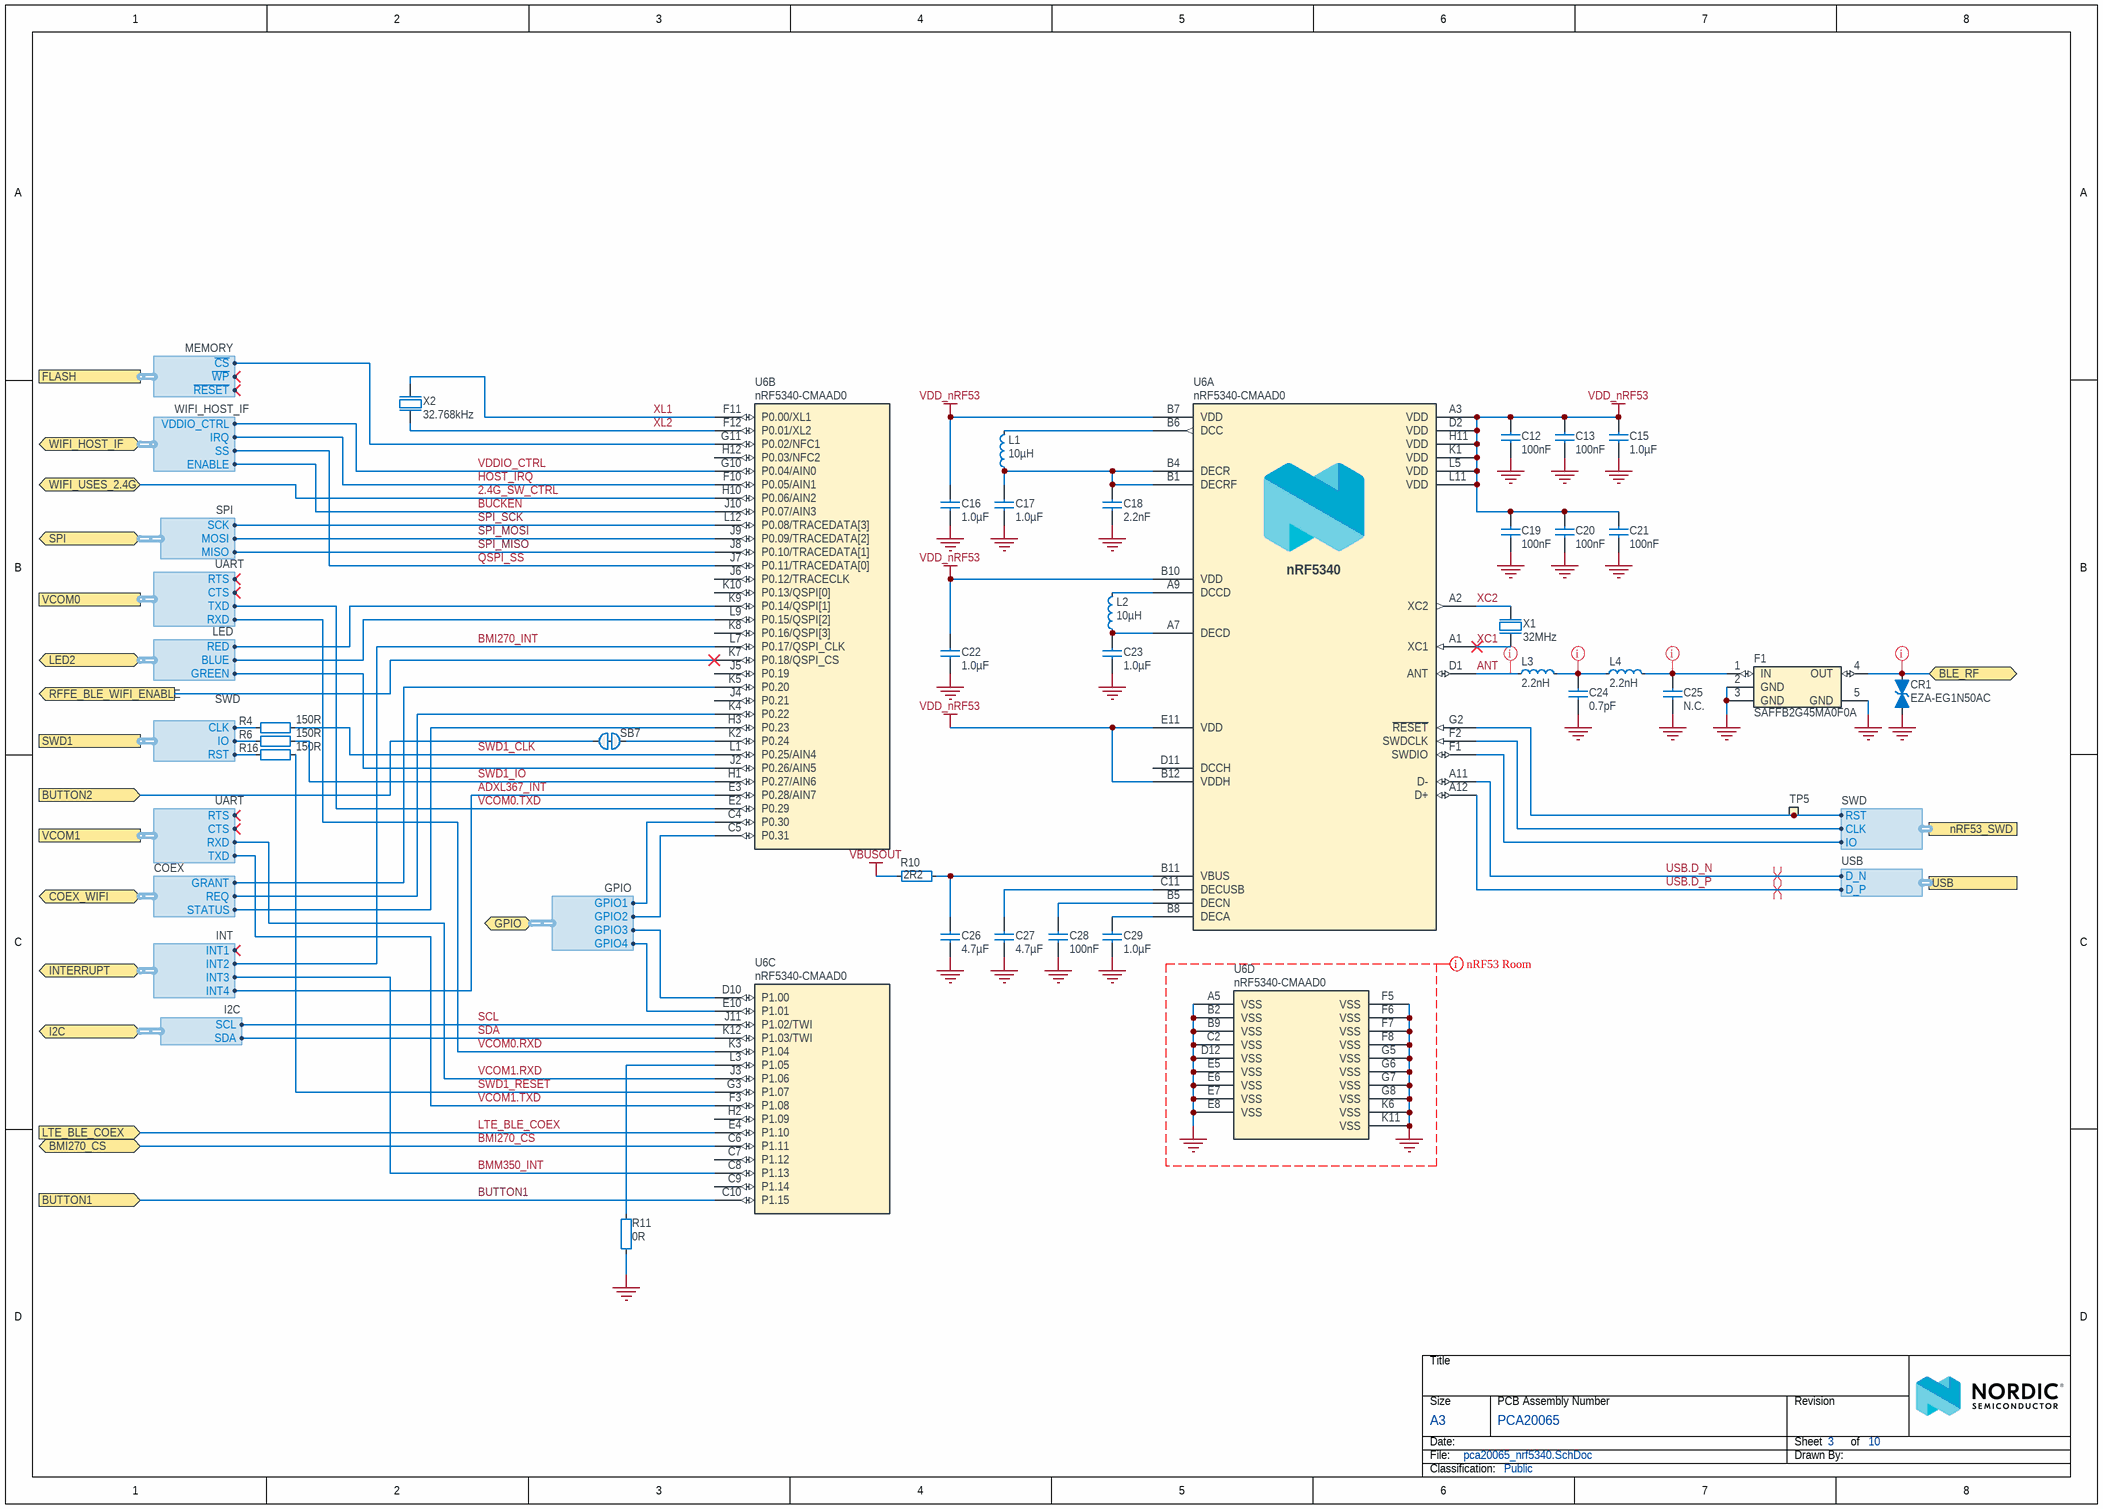
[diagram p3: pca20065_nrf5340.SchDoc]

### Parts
C12  100nF  [CAPC0603X03L_C]
C13  100nF  [CAPC0603X03L_C]
C15  1.0µF  [CAPC1005X04L]
C16  1.0µF  [CAPC1005X04L]
C17  1.0µF  [CAPC1005X04L]
C18  2.2nF  [CAPC0603X03L_C]
C19  100nF  [CAPC0603X03L_C]
C20  100nF  [CAPC0603X03L_C]
C21  100nF  [CAPC0603X03L_C]
C22  1.0µF  [CAPC1005X04L]
C23  1.0µF  [CAPC1005X04L]
C24  0.7pF  [CAPC0603X03L_C]
C25  N.C.  [CAPC0603X03L_C_NC]
C26  4.7µF  [CAPC1608X06L]
C27  4.7µF  [CAPC1608X06L]
C28  100nF  [CAPC0603X03L_C]
C29  1.0µF  [CAPC1005X04L]
CR1  EZA-EG1N50AC  [RESC0603X03L_C]
F1  SAFFB2G45MA0F0A  [SAFFB2G45MA0F0A]
L1  10µH  [INDC1608X06L]
L2  10µH  [INDC1608X06L]
L3  2.2nH  [INDC0603X03L_C]
L4  2.2nH  [INDC0603X03L_C]
R4  150R  [RESC0603X03L_C]
R6  150R  [RESC0603X03L_C]
R10  2R2  [RESC1005X04L]
R11  0R  [RESC0603X03L_C]
R16  150R  [RESC0603X03L_C]
SB7  Solderbridge  [Solderbridge_Shorted]  (value not drawn)  (net tie, no BOM)
TP5  Ø1.5mm,SMD  [TP_SMD_D1.5mm]  (value not drawn)  (no BOM)
U6  nRF5340-CMAAD0  [BGA95C35P12X11_439X399X49]  (parts A,B,C,D of 4)
X1  32MHz  [BT-XTAL_2016]
X2  32.768kHz  [XTAL_2012]

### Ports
BLE_RF (bidir), BMI270_CS (bidir), BUTTON1 (in), BUTTON2 (in), COEX_WIFI (bidir, harness COEX), FLASH (harness MEMORY), GPIO (bidir, harness GPIO), I2C (bidir, harness I2C), INTERRUPT (bidir, harness INT), LED2 (bidir, harness LED), LTE_BLE_COEX (in), nRF53_SWD (harness SWD), RFFE_BLE_WIFI_ENABLE (out), SPI (bidir, harness SPI), SWD1 (harness SWD), USB (harness USB), VCOM0 (harness UART), VCOM1 (harness UART), WIFI_HOST_IF (bidir, harness WIFI_HOST_IF), WIFI_USES_2.4G (bidir)

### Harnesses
I2C: SDA, SCL
SWD: IO, CLK, RST
USB: D_P, D_N
LED: BLUE, GREEN, RED
UART: RTS, CTS, RXD, TXD
WIFI_HOST_IF: SS, IRQ, ENABLE, VDDIO_CTRL
INT: INT2, INT3, INT1, INT4
COEX: STATUS, REQ, GRANT
SPI: MISO, MOSI, SCK
GPIO: GPIO2, GPIO3, GPIO1, GPIO4
MEMORY: ~{CS}, ~{WP}, ~{RESET}

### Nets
GND: C12.2 C13.2 C15.2 C16.2 C17.1 C18.2 C19.2 C20.2 C21.2 C22.1 C23.1 C24.1 C25.1 C26.2 C27.2 C28.2 C29.1 CR1.1 F1.2(GND) F1.3(GND) F1.5(GND) R11.1 U6.A5(VSS) U6.B2(VSS) U6.B9(VSS) U6.C2(VSS) U6.D12(VSS) U6.E5(VSS) U6.E6(VSS) U6.E7(VSS) U6.E8(VSS) U6.F5(VSS) U6.F6(VSS) U6.F7(VSS) U6.F8(VSS) U6.G5(VSS) U6.G6(VSS) U6.G7(VSS) U6.G8(VSS) U6.K6(VSS) U6.K11(VSS) X1.2(GND) X1.4(GND)
VBUSOUT: R10.1
VDD_nRF53: C12.1 C13.1 C15.1 C16.1 C19.1 C20.1 C21.1 C22.2 U6.A3(VDD) U6.B7(VDD) U6.B10(VDD) U6.B12(VDDH) U6.D2(VDD) U6.E11(VDD) U6.H11(VDD) U6.K1(VDD) U6.L5(VDD) U6.L11(VDD)
2.4G_SW_CTRL: U6.H10(P0.06/AIN2) ; port WIFI_USES_2.4G
ADXL367_INT: U6.E3(P0.28/AIN7) ; port INTERRUPT.INT4
ANT: L3.2 U6.D1(ANT)
BMI270_CS: U6.C6(P1.11) ; port BMI270_CS
BMI270_INT: U6.L7(P0.17/QSPI_CLK) ; port INTERRUPT.INT2
BMM350_INT: U6.C8(P1.13) ; port INTERRUPT.INT3
BUCKEN: U6.J10(P0.07/AIN3) ; port WIFI_HOST_IF.ENABLE
COEX_GRANT: U6.K5(P0.20) ; port COEX_WIFI.GRANT
COEX_REQ: U6.K4(P0.22) ; port COEX_WIFI.REQ
COEX_STATUS: U6.H3(P0.23) ; port COEX_WIFI.STATUS
FLASH_~{CS}: U6.G11(P0.02/NFC1) ; port FLASH.~{CS}
HOST_IRQ: U6.F10(P0.05/AIN1) ; port WIFI_HOST_IF.IRQ
LTE_BLE_COEX: U6.E4(P1.10) ; port LTE_BLE_COEX
MISO: U6.J8(P0.10/TRACEDATA[1]) ; port SPI.MISO
MOSI: U6.J9(P0.09/TRACEDATA[2]) ; port SPI.MOSI
P0.08/TRACEDATA3: U6.E10(P1.01) ; port GPIO.GPIO4
P0.09/TRACEDATA2: U6.D10(P1.00) ; port GPIO.GPIO3
P0.10/TRACEDATA1: U6.C5(P0.31) ; port GPIO.GPIO2
P0.11/TRACEDATA0: U6.C4(P0.30) ; port GPIO.GPIO1
QSPI_CLK: U6.L12(P0.08/TRACEDATA[3]) ; port SPI.SCK
QSPI_SS: U6.J7(P0.11/TRACEDATA[0]) ; port WIFI_HOST_IF.SS
RFFE_BLE_WIFI_ENABLE: U6.K7(P0.18/QSPI_CS) ; port RFFE_BLE_WIFI_ENABLE
SCL: U6.J11(P1.02/TWI) ; port I2C.SCL
SDA: U6.K12(P1.03/TWI) ; port I2C.SDA
SWD1_CLK: R4.1 U6.L1(P0.25/AIN4)
SWD1_IO: R6.1 U6.H1(P0.27/AIN6)
SWD1_RESET: R16.1 U6.G3(P1.07)
USB.D_N: U6.A11(D-) ; port USB.D_N
USB.D_P: U6.A12(D+) ; port USB.D_P
VCOM0.RXD: U6.K3(P1.04) ; port VCOM0.RXD
VCOM0.TXD: U6.E2(P0.29) ; port VCOM0.TXD
VCOM1.RXD: U6.J3(P1.06) ; port VCOM1.RXD
VCOM1.TXD: U6.F3(P1.08) ; port VCOM1.TXD
VDDIO_CTRL: U6.G10(P0.04/AIN0) ; port WIFI_HOST_IF.VDDIO_CTRL
XC1: U6.A1(XC1) X1.1(inp)
XC2: U6.A2(XC2) X1.3(out)
XL1: U6.F11(P0.00/XL1) X2.1(inp)
XL2: U6.F12(P0.01/XL2) X2.2(out)
NetC17_2: C17.2 C18.1 L1.1 U6.B1(DECRF) U6.B4(DECR)
NetC23_2: C23.2 L2.1 U6.A7(DECD)
NetC24_2: C24.2 L3.1 L4.2
NetC25_2: C25.2 F1.1(IN) L4.1
NetC26_1: C26.1 R10.2 U6.B11(VBUS)
NetC27_1: C27.1 U6.C11(DECUSB)
NetC28_1: C28.1 U6.B5(DECN)
NetC29_2: C29.2 U6.B8(DECA)
NetCR1_2: CR1.2 F1.4(OUT) ; port BLE_RF
NetL1_2: L1.2 U6.B6(DCC)
NetL2_2: L2.2 U6.A9(DCCD)
NetM1_44: U6.C10(P1.15) ; port BUTTON1
NetQ1_1: U6.J2(P0.26/AIN5) ; port LED2.GREEN
NetQ2_2: U6.K9(P0.14/QSPI[1]) ; port LED2.RED
NetQ2_5: U6.L9(P0.15/QSPI[2]) ; port LED2.BLUE
NetQ6_6: SB7.2 ; port BUTTON2
NetQ13_2: R16.2 ; port SWD1.RST
NetR4_2: R4.2 ; port SWD1.CLK
NetR6_2: R6.2 ; port SWD1.IO
NetR11_2: R11.2 U6.L3(P1.05)
NetSB6_2: TP5.1 U6.G2(~{RESET}) ; port nRF53_SWD.RST
NetSB7_1: SB7.1 U6.K2(P0.24)
NetU6_F1: U6.F1(SWDIO) ; port nRF53_SWD.IO
NetU6_F2: U6.F2(SWDCLK) ; port nRF53_SWD.CLK

Not connected (* = marked no-connect by the designer): U6 C7(P1.12) C9(P1.14) D11(DCCH) H2(P1.09) H12(P0.03/NFC2) J4(P0.21) J5(P0.19) J6(P0.12/TRACECLK) K8(P0.16/QSPI[3]) K10(P0.13/QSPI[0])

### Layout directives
differential pair: USB.D_N, USB.D_P
net class RF_BLE/WIFI: ANT, NetC24_2, NetC25_2, NetCR1_2
CompClassName: nRF53: GND

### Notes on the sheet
- SPI_SCK
- SPI_MOSI
- SPI_MISO
- BUTTON1

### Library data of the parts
C12 C13 C19-C21 C28 = C0201-100n: Capacitor, X5R, ±10%; Part number IPS: 00000001248, 00000002505; Part number Norautron: 262071862; Part number NEMS: 100200078; Pad Count: 2; Artikkelnr Noca: N.A.; Note: 16V; Component Status: Active
C15-C17 C22 C23 C29 = C0402-1µ0-10V-X5R: Capacitor, Ceramic, X5R, ±10%, 10V; Manufacturer: N.A.; Part number NEMS: 100200482; Pad Count: 2; Component Status: Active
C18 = C0201-2n2: Capacitor, X7R, ±10%, 10V; Part number IPS: 00000001778; Part number Norautron: 26470002; Part number NEMS: 100200060; Pad Count: 2; Artikkelnr Noca: N.A.; Component Status: Active
C24 = C0201-0.7p-50V-C0G-GJM0335C1HR70WB01: Capacitor, Ceramic, C0G, ±0.05pF, 50V; Manufacturer: Murata; Manufacturer Part Number: GJM0335C1HR70WB01D; Part number NEMS: 100200011; Pad Count: 2; Artikkelnr Noca: N.A.; Component Status: Active
C25 = C0201-N.C.: Not mounted; Part number NEMS: 100200001; Assembly: Not mounted; Pad Count: 2; Artikkelnr Noca: N.A.; Note: Chip Cap; Component Status: Active
C26 = C0603-4µ7-10V-X7S: Capacitor, X7S, ±10%, 10V; Manufacturer: N.A.; Part number IPS: 00000001779; Part number NEMS: 100200351; Pad Count: 2; Artikkelnr Noca: 20030013; Component Status: Active
C27 = C0603-4µ7-6.3V-X7R: Capacitor, X7R, ±10%, 6.3V; Manufacturer: Samsung Electro-Mechanics America; Manufacturer Part Number: CL10B475KQ8NQNC; Part number IPS: 00000002541; Part number Norautron: N.A.; Part number NEMS: 100200350; Pad Count: 2; Artikkelnr Noca: 20039473; Component Status: Active
CR1 = EZA-EG1N50AC: ESD Suppressor, 30V, 0.04pF; Manufacturer: Panasonic; Part number IPS: 00000004437; Part number NEMS: 101300173; Note: N.A.; Pad Count: 2; Component Status: Active
F1 = SAFFB2G45MA0F0A: 2.4 GHz BPF; Manufacturer: Murata; Part number IPS: 00000001784, 80000001660; Part number NEMS: 100800023; Artikkelnr Noca: N.A.; Pad Count: 5; Component Status: Active
L1 L2 = L0603-10µ: Inductor, 80mA, ±10%; Manufacturer: Taiyo Yuden; Manufacturer Part Number: LBMF1608T100K; Part number IPS: 00000007794; Part number Norautron: N.A.; Part number NEMS: 100300078; Pad Count: 2; Artikkelnr Noca: 33029314; Note: LBMF1608T100K 10µH 80mA 0603; Component Status: Active
L3 L4 = L0201-2n2: Chip Inductor; Part number NEMS: 100300017; Pad Count: 2; Artikkelnr Noca: N.A.; Note: High frequency chip inductor ±5%; Component Status: Active
R4 R6 R16 = R0201-150: Resistor, ±1%, 0.05W; Manufacturer: N.A.; Part number IPS: 00000001420; Part number NEMS: 100100029; Note: Chip Res 1%; Pad Count: 2; Component Status: Active
R10 = R0402-2R2-0.1W: Resistor, ±1%, 0.1W; Pad Count: 2; Artikkelnr Noca: N.A.; Note: 2R2 1% 0.1W; Component Status: Active
R11 = R0201-0R: Resistor, ±5%, 0.05W; Manufacturer: N.A.; Part number IPS: 00000003245; Part number NEMS: 100100001; Pad Count: 2; Note: Chip Res 5%; Component Status: Active
SB7 = Solderbridge Shorted: as SB6 on sheet pca20065_nrf9151
TP5 = TP_SMD_Ø1.5MM: as TP32 on sheet pca20065_nrf9151
U6 = nRF5340-CMAAD0: Multi-protocol Bluetooth Low Energy, IEEE 802.15.4, ANT and 2.4GHz proprietary system-on-chip; Manufacturer: Nordic Semiconductor; Part number NEMS: 102000337; Pad Count: 95; Note: N.A.; Component Status: Active
X1 = XTAL_SMD2016_32MHz_8pF_Kyocera_SA: XTAL SMD 2016, 32MHz, Cl=8pF, ±30ppm, -40°C ~ 105°C; Manufacturer Part Number: CX2016SA32000D0WRQG1; Part number NEMS: 101600100; Pad Count: 4; Artikkelnr Noca: N.A.; Note: XTAL SMD 32.000MHz; Component Status: Active
X2 = XTAL_SMD2012_32.768kHz_9pF_Golledge: XTAL SMD 2012, 32.768kHz, 9pF, ±20ppm; Manufacturer Part Number: MP07668; Part number Norautron: 26470047; Part number NEMS: 101600017; Pad Count: 2; Artikkelnr Noca: N.A.; Note: XTAL SMD 32.768kHz; Component Status: Active

## Sheet pca20065_interface.SchDoc: =BoardTitle + ' - Interface'
size A3; Organization: Nordic Semiconductor; DocumentNumber: 8; Revision: 2.0.0; SheetNumber: 8; SheetTotal: 10; Author: GETR; CompanyName: Nordic Semiconductor; DrawnBy: GETR; DocumentSize: A3
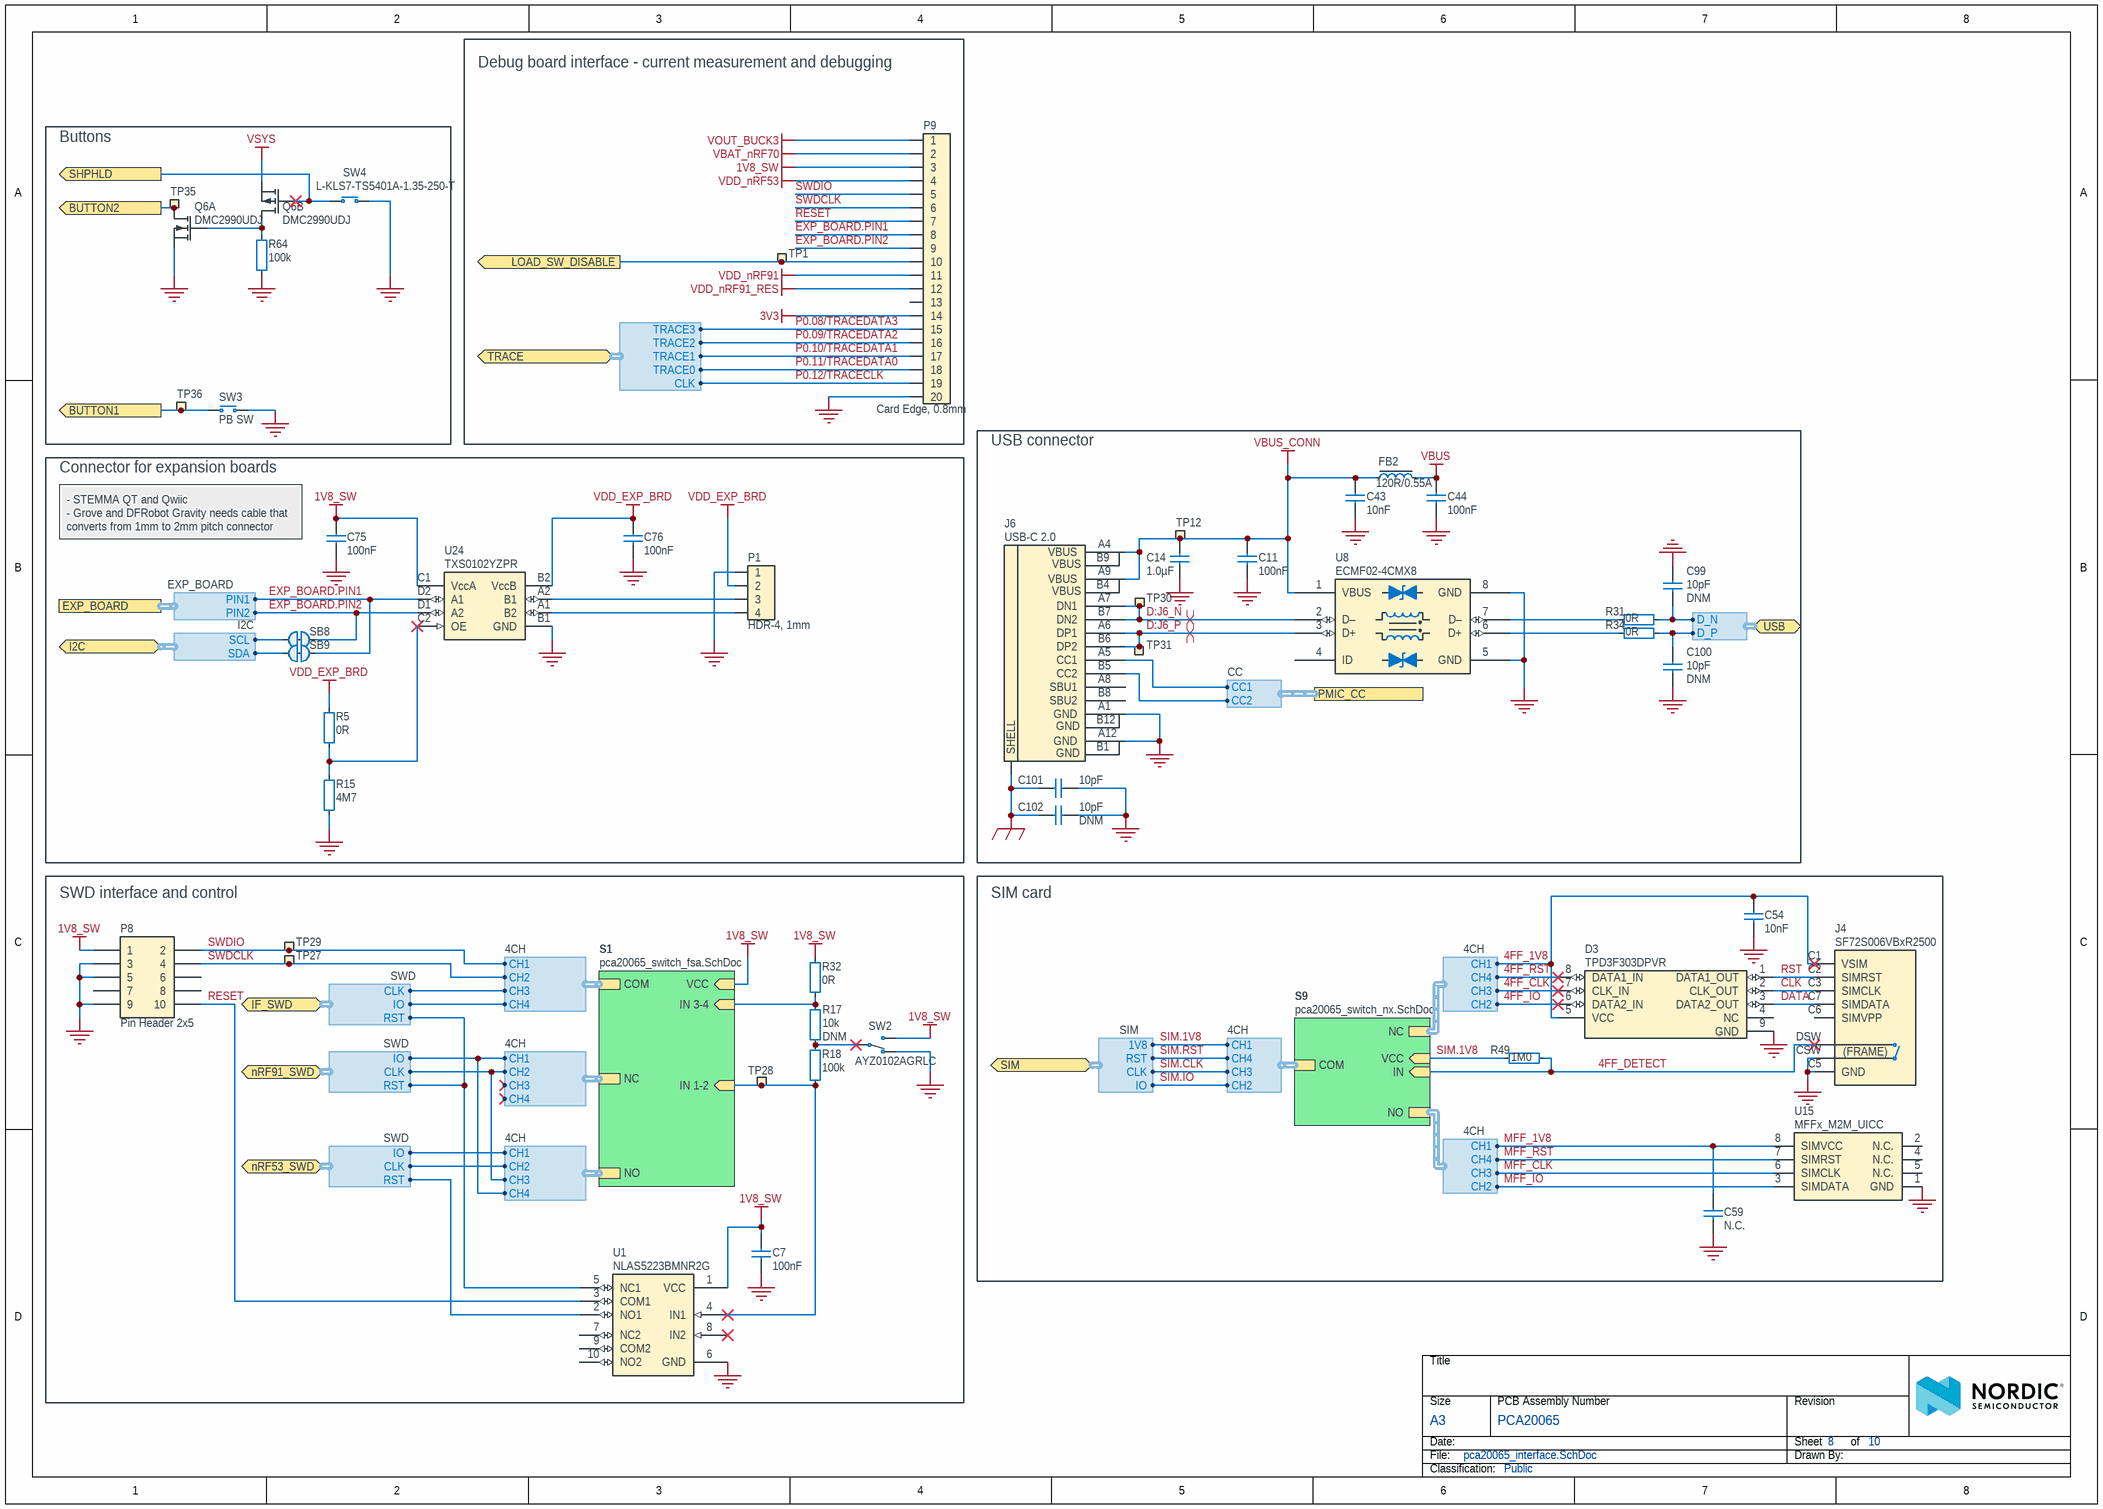
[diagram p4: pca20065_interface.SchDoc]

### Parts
C7  100nF  [CAPC0603X03L_C]
C11  100nF  [CAPC0603X03L_C]
C14  1.0µF  [CAPC1005X04L]
C43  10nF  [CAPC0603X03L_C]
C44  100nF  [CAPC0603X03L_C]
C54  10nF  [CAPC0603X03L_C]
C59  N.C.  [CAPC0603X03L_C_NC]
C75  100nF  [CAPC0603X03L_C]
C76  100nF  [CAPC0603X03L_C]
C99  10pF  Assembly: DNM  [CAPC0603X03L_C]
C100  10pF  Assembly: DNM  [CAPC0603X03L_C]
C101  10pF  [CAPC0603X03L_C]
C102  10pF  Assembly: DNM  [CAPC0603X03L_C]
D3  TPD3F303DPVR  [SON50P210X160X65_HS-9N]
FB2  120R/0.55A  [INDC1005X04L]
J4  SF72S006VBxR2500  [SF72S006VBxR2500]
J6  USB-C 2.0  [USB4110]
P1  HDR-4, 1mm  [SM04B-SRSS-TB]
P8  Pin Header 2x5  [HDR_2x5-SMD-1.27mm-ANG]
P9  Card Edge, 0.8mm  [10056847-101LF]
Q6  DMC2990UDJ  [DMx299UDJ]  (parts A,B of 2)
R5  0R  [RESC0603X03L_C]
R15  4M7  [RESC0603X03L_C]
R17  10k  Assembly: DNM  [RESC0603X03L_C]
R18  100k  [RESC0603X03L_C]
R31  0R  [RESC0603X03L_C]
R32  0R  [RESC0603X03L_C]
R34  0R  [RESC0603X03L_C]
R49  1M0  [RESC0603X03L_C]
R64  100k  [RESC0603X03L_C]
SB8  Solderbridge  [Solderbridge_Shorted]  (value not drawn)  (net tie, no BOM)
SB9  Solderbridge  [Solderbridge_Shorted]  (value not drawn)  (net tie, no BOM)
SW2  AYZ0102AGRLC  [AYZ0102AGRLC]
SW3  PB SW  [L-KLS7-TS6616B-2.5-160-T]
SW4  L-KLS7-TS5401A-1.35-250-T  [L-KLS7-TS5401A-1.35-250-T]
TP1  Ø1.5mm,SMD  [TP_SMD_D1.5mm]  (value not drawn)  (no BOM)
TP12  Ø1.5mm,SMD  [TP_SMD_D1.5mm]  (value not drawn)  (no BOM)
TP27  Ø1.5mm,SMD  [TP_SMD_D1.5mm]  (value not drawn)  (no BOM)
TP28  Ø1.5mm,SMD  [TP_SMD_D1.5mm]  (value not drawn)  (no BOM)
TP29  Ø1.5mm,SMD  [TP_SMD_D1.5mm]  (value not drawn)  (no BOM)
TP30  Ø1.5mm,SMD  [TP_SMD_D1.5mm]  (value not drawn)  (no BOM)
TP31  Ø1.5mm,SMD  [TP_SMD_D1.5mm]  (value not drawn)  (no BOM)
TP35  Ø1.5mm,SMD  [TP_SMD_D1.5mm]  (value not drawn)  (no BOM)
TP36  Ø1.5mm,SMD  [TP_SMD_D1.5mm]  (value not drawn)  (no BOM)
U1  NLAS5223BMNR2G  [UFQFN40P140X180X55-10N]
U8  ECMF02-4CMX8  [UFDFN50P120X250X55-8N]
U15  MFFx_M2M_UICC  [SON127P600X90_HS-8N]
U24  TXS0102YZPR  [BGA8C50P2X4_89X189X50]

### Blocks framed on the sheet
Debug board interface - current measurement and debugging: P9 TP1
Buttons: Q6 R64 SW3 SW4 TP35 TP36
USB connector: C11 C14 C43 C44 C99-C102 FB2 J6 R31 R34 TP12 TP30 TP31 U8
Connector for expansion boards: C75 C76 P1 R5 R15 SB8 SB9 U24
SWD interface and control: C7 P8 R17 R18 R32 SW2 TP27-TP29 U1
SIM card: C54 C59 D3 J4 R49 U15

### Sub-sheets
S1 = pca20065_switch_fsa.SchDoc: IN 1-2 (in), COM (harness 4CH), NC (harness 4CH), NO (harness 4CH), IN 3-4 (in), VCC (in)
S9 = pca20065_switch_nx.SchDoc: IN (in), COM (harness 4CH), NC (harness 4CH), NO (harness 4CH), VCC (in)

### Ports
BUTTON1 (out), BUTTON2 (out), EXP_BOARD (harness EXP_BOARD), I2C (bidir, harness I2C), IF_SWD (bidir, harness SWD), LOAD_SW_DISABLE (out), nRF53_SWD (bidir, harness SWD), nRF91_SWD (bidir, harness SWD), PMIC_CC (harness CC), SHPHLD (out), SIM (bidir, harness SIM), TRACE (bidir, harness TRACE), USB (bidir, harness USB)

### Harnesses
SWD: IO, CLK, RST
SIM: RST, CLK, IO, 1V8
USB: D_N, D_P
EXP_BOARD: PIN1, PIN2
CC: CC2, CC1
4CH: CH1, CH2, CH3, CH4
I2C: SDA, SCL
TRACE: TRACE3, TRACE2, TRACE1, TRACE0, CLK

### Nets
1V8_SW: C7.1 C75.2 P8.1 P9.3 R32.1 SW2.3(N.O) U1.1(VCC) U24.C1(VccA) ; sheet S1/VCC
3V3: P9.14
GND: C7.2 C11.1 C14.1 C43.1 C44.1 C54.2 C59.1 C75.1 C76.1 C99.2 C100.2 C101.1 C102.1 D3.9(GND) J4.0(GND) J4.C5(GND) J4.CSW J6.A1(GND) J6.A12(GND) P1.1 P8.3 P8.5 P8.9 P9.20 Q6.1(S1) R15.2 R64.2 SW2.1(N.C) SW3.1(N.O) SW4.2(COM) U1.6(GND) U8.5(GND) U8.8(GND) U15.1(GND) U24.B1(GND)
Shield: C101.2 C102.2 J6.SHLD(SHELL)
VBAT_nRF70: P9.2
VBUS: C44.2 FB2.2
VBUS_CONN: C11.2 C14.2 C43.2 FB2.1 J6.A4(VBUS) J6.A9(VBUS) TP12.1 U8.1(VBUS)
VDD_EXP_BRD: C76.2 P1.2 R5.1 U24.B2(VccB)
VDD_nRF53: P9.4
VDD_nRF91: P9.11
VDD_nRF91_RES: P9.12
VOUT_BUCK3: P9.1
VSYS: Q6.4(S2)
4FF_1V8: C54.1 D3.5(VCC) J4.C1(VSIM) ; sheet S9/NC.CH1
4FF_CLK: D3.7(CLK_IN) ; sheet S9/NC.CH3
4FF_DETECT: J4.DSW R49.1 ; sheet S9/IN
4FF_IO: D3.6(DATA2_IN) ; sheet S9/NC.CH2
4FF_RST: D3.8(DATA1_IN) ; sheet S9/NC.CH4
CC1: J6.A5(CC1) ; port PMIC_CC.CC1
CC2: J6.B5(CC2) ; port PMIC_CC.CC2
CLK: D3.2(CLK_OUT) J4.C3(SIMCLK)
D:J6_N: J6.A7(DN1) J6.B7(DN2) TP30.1 U8.2(D–)
D:J6_P: J6.A6(DP1) J6.B6(DP2) TP31.1 U8.3(D+)
DATA: D3.3(DATA2_OUT) J4.C7(SIMDATA)
EXP_BOARD.PIN1: P9.8 SB9.1 U24.D2(A1) ; port EXP_BOARD.PIN1
EXP_BOARD.PIN2: P9.9 SB8.1 U24.D1(A2) ; port EXP_BOARD.PIN2
MFF_1V8: C59.2 U15.8(SIMVCC) ; sheet S9/NO.CH1
MFF_CLK: U15.6(SIMCLK) ; sheet S9/NO.CH3
MFF_IO: U15.3(SIMDATA) ; sheet S9/NO.CH2
MFF_RST: U15.7(SIMRST) ; sheet S9/NO.CH4
P0.08/TRACEDATA3: P9.15 ; port TRACE.TRACE3
P0.09/TRACEDATA2: P9.16 ; port TRACE.TRACE2
P0.10/TRACEDATA1: P9.17 ; port TRACE.TRACE1
P0.11/TRACEDATA0: P9.18 ; port TRACE.TRACE0
P0.12/TRACECLK: P9.19 ; port TRACE.CLK
RESET: P8.10 P9.7 U1.3(COM1)
RST: D3.1(DATA1_OUT) J4.C2(SIMRST)
SCL: SB8.2 ; port I2C.SCL
SDA: SB9.2 ; port I2C.SDA
SHPHLD: Q6.5(G2) SW4.1(N.O) ; port SHPHLD
SIM.1V8: R49.2 ; sheet S9/VCC, port SIM.1V8, sheet S9/COM.CH1
SIM.CLK: port SIM.CLK, sheet S9/COM.CH3
SIM.IO: port SIM.IO, sheet S9/COM.CH2
SIM.RST: port SIM.RST, sheet S9/COM.CH4
SWDCLK: P8.4 P9.6 TP27.1 ; sheet S1/COM.CH2
SWDIO: P8.2 P9.5 TP29.1 ; sheet S1/COM.CH1
USB.D_N: C99.1 R31.1 ; port USB.D_N
USB.D_P: C100.1 R34.1 ; port USB.D_P
NetM1_3: port nRF91_SWD.CLK, sheet S1/NO.CH3, sheet S1/NC.CH2
NetM1_4: port nRF91_SWD.IO, sheet S1/NO.CH4, sheet S1/NC.CH1
NetM1_44: SW3.2(COM) TP36.1 ; port BUTTON1
NetP1_3: P1.3 U24.A2(B1)
NetP1_4: P1.4 U24.A1(B2)
NetP9_10: P9.10 TP1.1 ; port LOAD_SW_DISABLE
NetQ6_2: Q6.2(G1) Q6.3(D2) R64.1
NetQ6_6: Q6.6(D1) TP35.1 ; port BUTTON2
NetQ13_2: U1.5(NC1) ; port nRF91_SWD.RST, port IF_SWD.RST
NetR4_2: sheet S1/COM.CH3, port IF_SWD.CLK
NetR5_2: R5.2 R15.1 U24.C2(OE)
NetR6_2: sheet S1/COM.CH4, port IF_SWD.IO
NetR17_1: R17.1 R32.2 ; sheet S1/IN 3-4
NetR17_2: R17.2 R18.1 SW2.2(COM)
NetR18_2: R18.2 TP28.1 U1.4(IN1) ; sheet S1/IN 1-2
NetR31_2: R31.2 U8.7(D–)
NetR34_2: R34.2 U8.6(D+)
NetSB6_2: U1.2(NO1) ; port nRF53_SWD.RST
NetU6_F1: port nRF53_SWD.IO, sheet S1/NO.CH1
NetU6_F2: port nRF53_SWD.CLK, sheet S1/NO.CH2

Not connected (* = marked no-connect by the designer): D3 4(NC); J4 C6(SIMVPP); J6 A8(SBU1) B8(SBU2); P8 6 7 8; P9 13; U1 7(NC2) 8(IN2)* 9(COM2) 10(NO2); U8 4(ID); U15 2(N.C.) 4(N.C.) 5(N.C.)

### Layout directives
differential pair: D:J6_N, D:J6_P

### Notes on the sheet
- (near C75) - STEMMA QT and Qwiic
  - Grove and DFRobot Gravity needs cable that converts from 1mm to 2mm pitch connector

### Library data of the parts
C7 = C0201-100n: as C33 on sheet pca20065_nrf9151
C11 C44 = C0201-100n-25V-X5R: Capacitor, Ceramic, X5R, ±10%, 25V; Manufacturer: Murata; Manufacturer Part Number: GRM033R61E104KE14J; Part number NEMS: 100200459; Artikkelnr Noca: N.A.; Pad Count: 2; Component Status: Active
C14 = C0402-1µ0-10V-X5R: as C15 on sheet pca20065_nrf5340
C43 = C0201-10n-25V-X5R: Capacitor, Ceramic, X5R, ±10%, 25V; Manufacturer: Murata; Manufacturer Part Number: GRM033R61E103KA12D; Part number NEMS: 100200458; Artikkelnr Noca: N.A.; Pad Count: 2; Component Status: Active
C54 = C0201-10n: Capacitor, X7R, ±10%; Manufacturer: N.A.; Part number IPS: 00000003480; Part number Norautron: 26621779; Part number NEMS: 100200067; Note: 10V; Pad Count: 2; Component Status: Active
C59 = C0201-N.C.: Not mounted; Manufacturer: N.A.; Part number NEMS: 100200001; Note: Chip Cap; Assembly: Not mounted; Pad Count: 2; Component Status: Active
C75 C76 = C0201-100n-25V-X5R: Capacitor, Ceramic, X5R, ±10%, 25V; Manufacturer: Murata; Manufacturer Part Number: GRM033R61E104KE14J; Part number NEMS: 100200459; Pad Count: 2; Artikkelnr Noca: N.A.; Component Status: Active
C99-C102 = C0201-10p: Capacitor, C0G, ±5%, 25V; Manufacturer: Murata; Manufacturer Part Number: GRM0335C1E100JA01D; Part number IPS: 00000003191; Part number NEMS: 100200032; Note: Chip Cap 1%; Artikkelnr Noca: N.A.; Pad Count: 2; Component Status: Active
D3 = TPD3F303DPVR: ESD Protection and EMI Filter for SIM Card Interface; Manufacturer: Texas Instruments; Part number NEMS: 101900729; Note: N.A.; Pad Count: 8; Component Status: Active
FB2 = FB0402-120R@100M-500mA: Ferrite Bead, 120 Ohm @ 100MHz, 500mA, 250 mOhm Max; Manufacturer: Murata; Manufacturer Part Number: BLM15AG121SN1D; Part number IPS: 00000009954; Part number Norautron: 265230631; Part number NEMS: 100300099; Note: Chip EMIFIL Inductor Type Chip Ferrite Bead; Artikkelnr Noca: 33029317; Pad Count: 2; Component Status: Active
J4 = SF72S006VBDR2500: n 8 (6 + 2) Position Card Connector NANO SIM Surface Mount, Right Angle Gold; Manufacturer: JAE Electronics; Part number NEMS: 100500780; Note: N.A.; Pad Count: 8; Component Status: Active
J6 = USB4110-GF-A: USB-C Receptacle, 16 Pin, USB 2.0; Manufacturer: Global Connector Technology; Part number NEMS: 100500735; Pad Count: 16; Note: N.A.; Component Status: Active; System: Connector
P1 = A1002WR-S-4P-LCP: 1.0mm pitch connector side entry SMD; Manufacturer: CJT; Part number NEMS: 100500540; Note: N.A.; Pad Count: 4; Component Status: Active
P8 = Pin Header 2x5 SMD, 1.27mm, Angled: Pin Header 2x5, 1.27mm (50mil); Manufacturer: WCON; Manufacturer Part Number: 1325B-1205S0Z080CR04; Part number NEMS: 100500257; Note: (Replaced 1325B-1205S0Z080CR02); Artikkelnr Noca: N.A.; Pad Count: 10; Component Status: Active; System: Connector
P9 = 10056847-101LF: 0.8mm pitch, dual edge, right angle, SMD, card edge connector; Manufacturer: FCI; Part number NEMS: 100500633; Note: N.A.; Pad Count: 20; Component Status: Active
Q6 = DMC2990UDJ-7: as Q13 on sheet pca20065_nrf9151
R5 R31 R32 R34 = R0201-0R: Resistor, ±5%, 0.05W; Manufacturer: N.A.; Part number IPS: 00000003245; Part number NEMS: 100100001; Note: Chip Res 5%; Pad Count: 2; Component Status: Active
R15 = R0201-4M7: Resistor, ±1%, 0.05W; Manufacturer: N.A.; Part number NEMS: 100100101; Note: Chip Res 1%; Pad Count: 2; Component Status: Active
R17 = R0201-10k: as R106 on sheet pca20065_nrf9151
R18 R64 = R0201-100k: as R107 on sheet pca20065_nrf9151
R49 = R0201-1M0: as R54 on sheet pca20065_nrf9151
SB8 SB9 = Solderbridge Shorted: as SB6 on sheet pca20065_nrf9151
SW2 = AYZ0102AGRLC: Miniature slide switch, SPDT, Right-Angle, ON-ON, 12V, 100mA; Manufacturer: C&K; Part number IPS: 00000002488; Part number NEMS: 101500120; Note: N.A.; Pad Count: 3; Component Status: Active
SW3 = L-KLS7-TS6616B-2.5-160-T: Tactile Switch, SPNO, SMD, 160gf, 6.2x6.4x2.5mm; Manufacturer: KLS; Part number NEMS: 101500133, 101500001; Note: N.A.; Pad Count: 4; Component Status: Active
SW4 = L-KLS7-TS5401A-1.35-250-T: Microminiature SMT Switch, Side Actuated; Manufacturer: Cabcon; Part number NEMS: 101500149; Pad Count: 4; Note: Tactile Switch, SPST, SMD, 220gf; Artikkelnr Noca: N.A.; Component Status: Active
TP1 TP12 TP27-TP31 = TP_SMD_Ø1.5MM: as TP32 on sheet pca20065_nrf9151
TP35 TP36 = TP_SMD_Ø1.5MM: 1.5mm circular SMD testpad; Manufacturer: Nordic Semiconductor; Manufacturer Part Number: N.A.; Part number NEMS: 100500477; Pad Count: 1; Component Status: Active; System: Connector
U1 = NLAS5223BMNR2G: Dual-SPDT Analog Switch; Manufacturer: ON Semiconductor; Part number NEMS: 101900819; Note: N.A.; Pad Count: 10; Component Status: Active
U8 = ECMF02-4CMX8: 2 Line Common mode filter with ESD protection for USB 2.0 interface; Manufacturer: STMicroelectronics; Part number NEMS: 100800034; Component Status: Active; Pad Count: 8; Note: N.A.
U15 = M2M_UICC: M2M UICC SIM Card; Manufacturer: N.A.; Part number NEMS: 101900595; Pad Count: 8; Component Status: Active
U24 = TXS0102YZPR: Voltage Level Translator Bidirectional 1 Circuit 2 Channel 24Mbps 8-DSBGA; Manufacturer: Texas Instruments; Part number NEMS: 101900724; Pad Count: 8; Note: TEXAS INSTRUMENTS - TXS0102YZTR - IC, TRANSLATOR; Artikkelnr Noca: N.A.; Component Status: Active

## Sheet pca20065_switch_fsa.SchDoc: =BoardTitle + ' - Switch FSA'
size A3; Organization: Nordic Semiconductor; DocumentNumber: 9; Revision: 2.0.0; SheetNumber: 9; SheetTotal: 10; Author: GETR; CompanyName: Nordic Semiconductor; DrawnBy: GETR; DocumentSize: A4
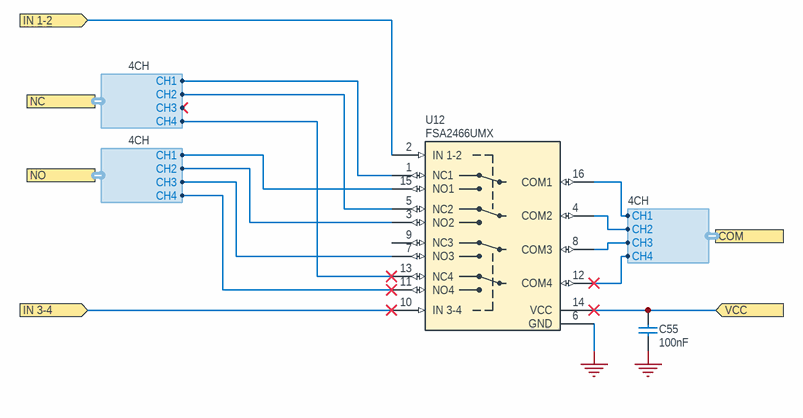
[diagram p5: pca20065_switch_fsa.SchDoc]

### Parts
C55  100nF  [CAPC0603X03L_C]
U12  FSA2466UMX  [XQFN40P180X260X50-16N]

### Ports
COM (harness 4CH), IN 1-2 (in), IN 3-4 (in), NC (harness 4CH), NO (harness 4CH), VCC (in)

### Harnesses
4CH: CH1, CH2, CH3, CH4

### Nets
1V8_SW: C55.1 U12.14(VCC) ; port VCC
GND: C55.2 U12.6(GND)
SWDCLK: U12.4(COM2) ; port COM.CH2
SWDIO: U12.16(COM1) ; port COM.CH1
NetM1_3: U12.5(NC2) U12.7(NO3) ; port NC.CH2, port NO.CH3
NetM1_4: U12.1(NC1) U12.11(NO4) ; port NC.CH1, port NO.CH4
NetR4_2: U12.8(COM3) ; port COM.CH3
NetR6_2: U12.12(COM4) ; port COM.CH4
NetR17_1: U12.10(IN_3-4) ; port IN 3-4
NetR18_2: U12.2(IN_1-2) ; port IN 1-2
NetU6_F1: U12.15(NO1) ; port NO.CH1
NetU6_F2: U12.3(NO2) ; port NO.CH2
NetU12_13: U12.13(NC4) ; port NC.CH4

Not connected (* = marked no-connect by the designer): U12 9(NC3)

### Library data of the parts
C55 = C0201-100n: as C33 on sheet pca20065_nrf9151
U12 = FSA2466UMX: Data / Audio Low-Voltage Dual DPDT Analog Switch; Manufacturer: ON Semiconductor; Part number IPS: 00000009986; Part number Norautron: 26500608; Part number NEMS: 101900422; Note: N.A.; Artikkelnr Noca: 15070069; Pad Count: 16; Component Status: Active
